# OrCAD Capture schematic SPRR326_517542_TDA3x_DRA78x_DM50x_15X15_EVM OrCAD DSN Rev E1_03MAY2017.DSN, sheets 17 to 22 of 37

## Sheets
17 SH25 - VOUT HDMI OUTPUT: size C; rev: A
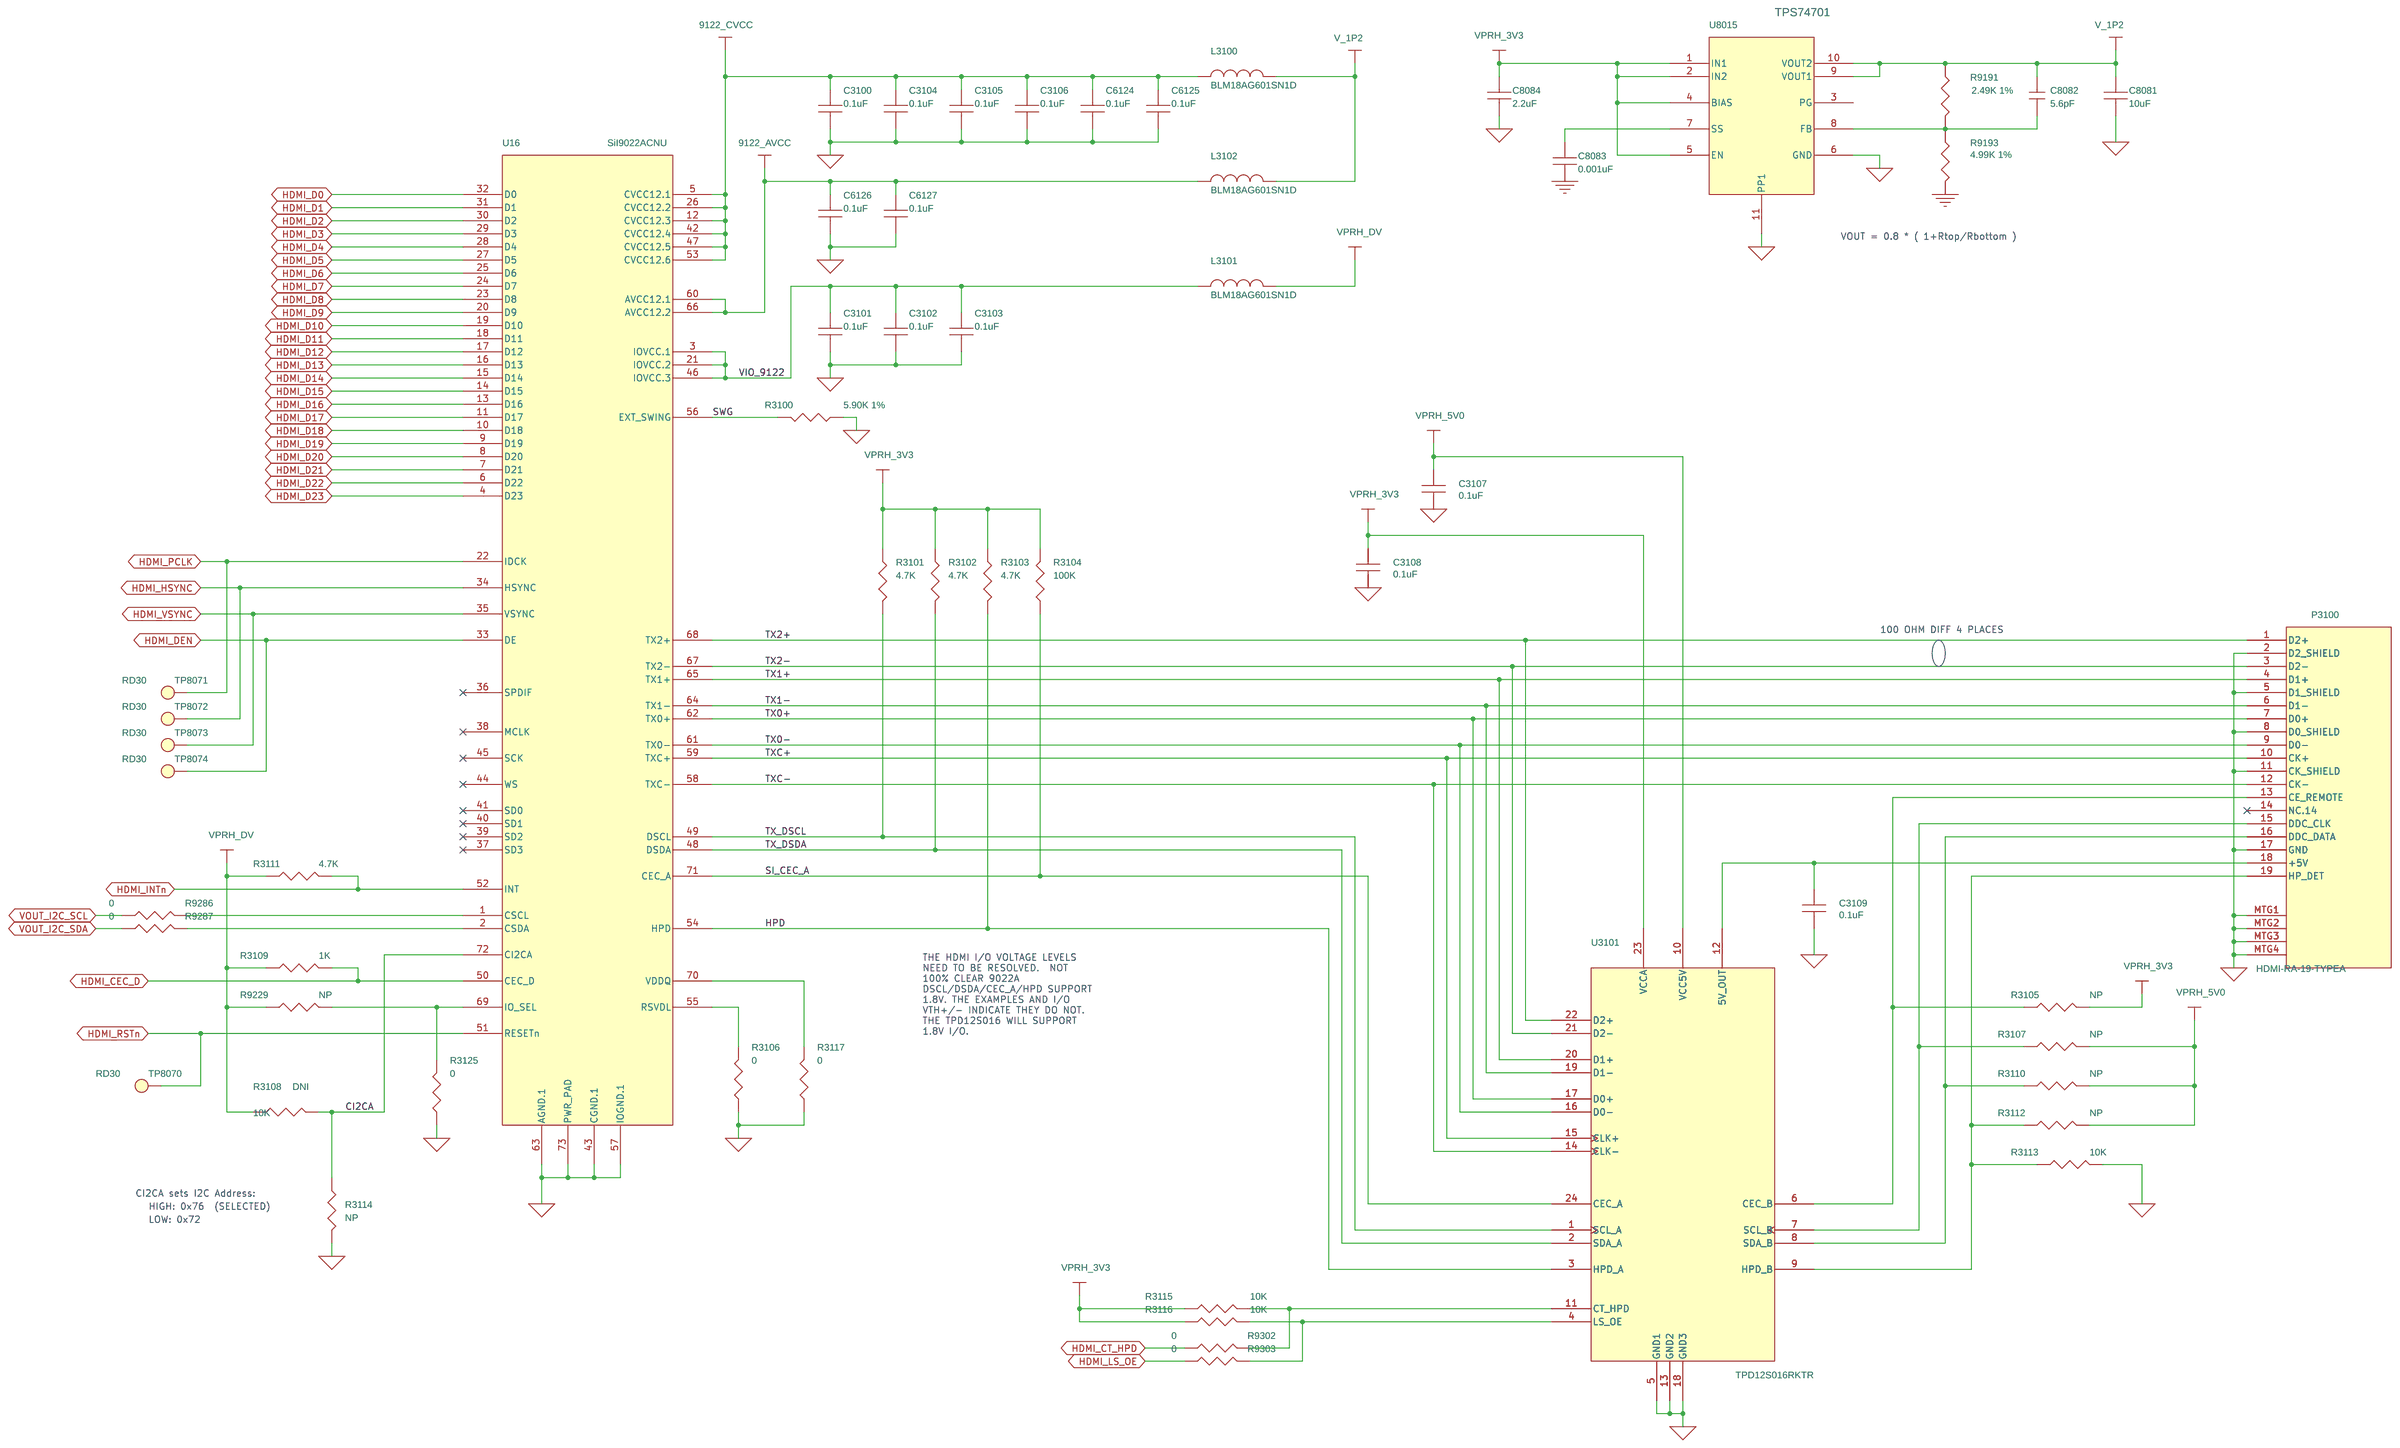
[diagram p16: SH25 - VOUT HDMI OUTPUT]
18 SH26 - VOUT FPD LINK: size C; rev: A
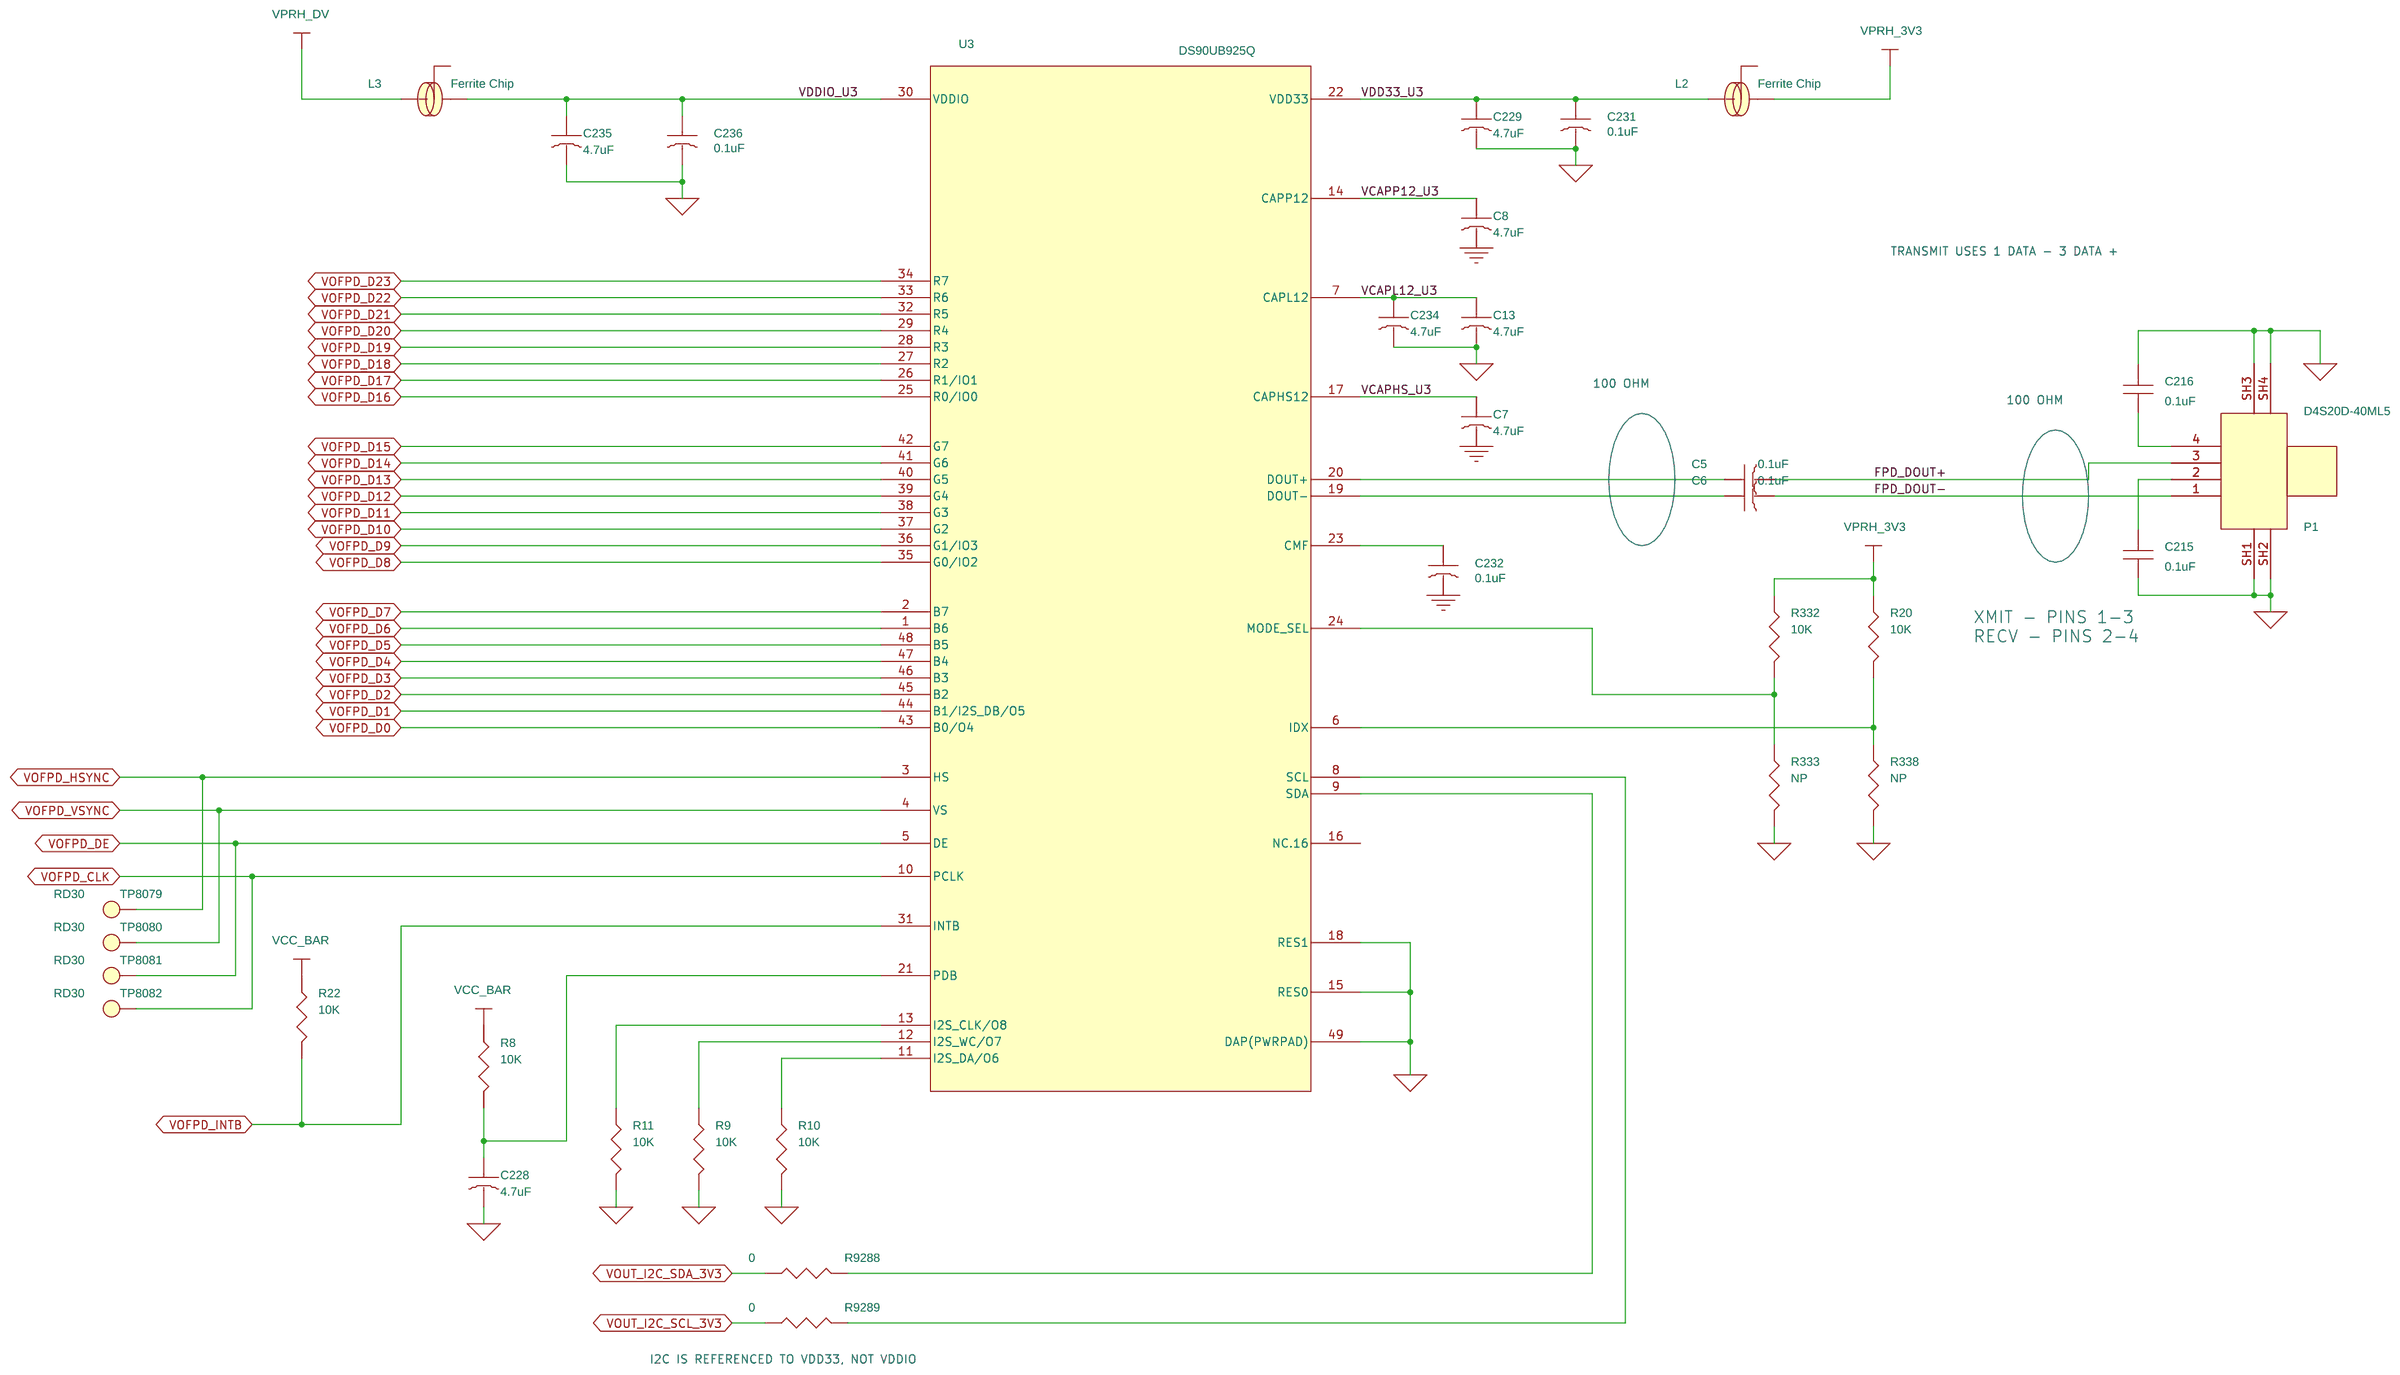
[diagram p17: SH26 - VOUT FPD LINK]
19 SH27 - VIN DS90UH926Q: size C; rev: A
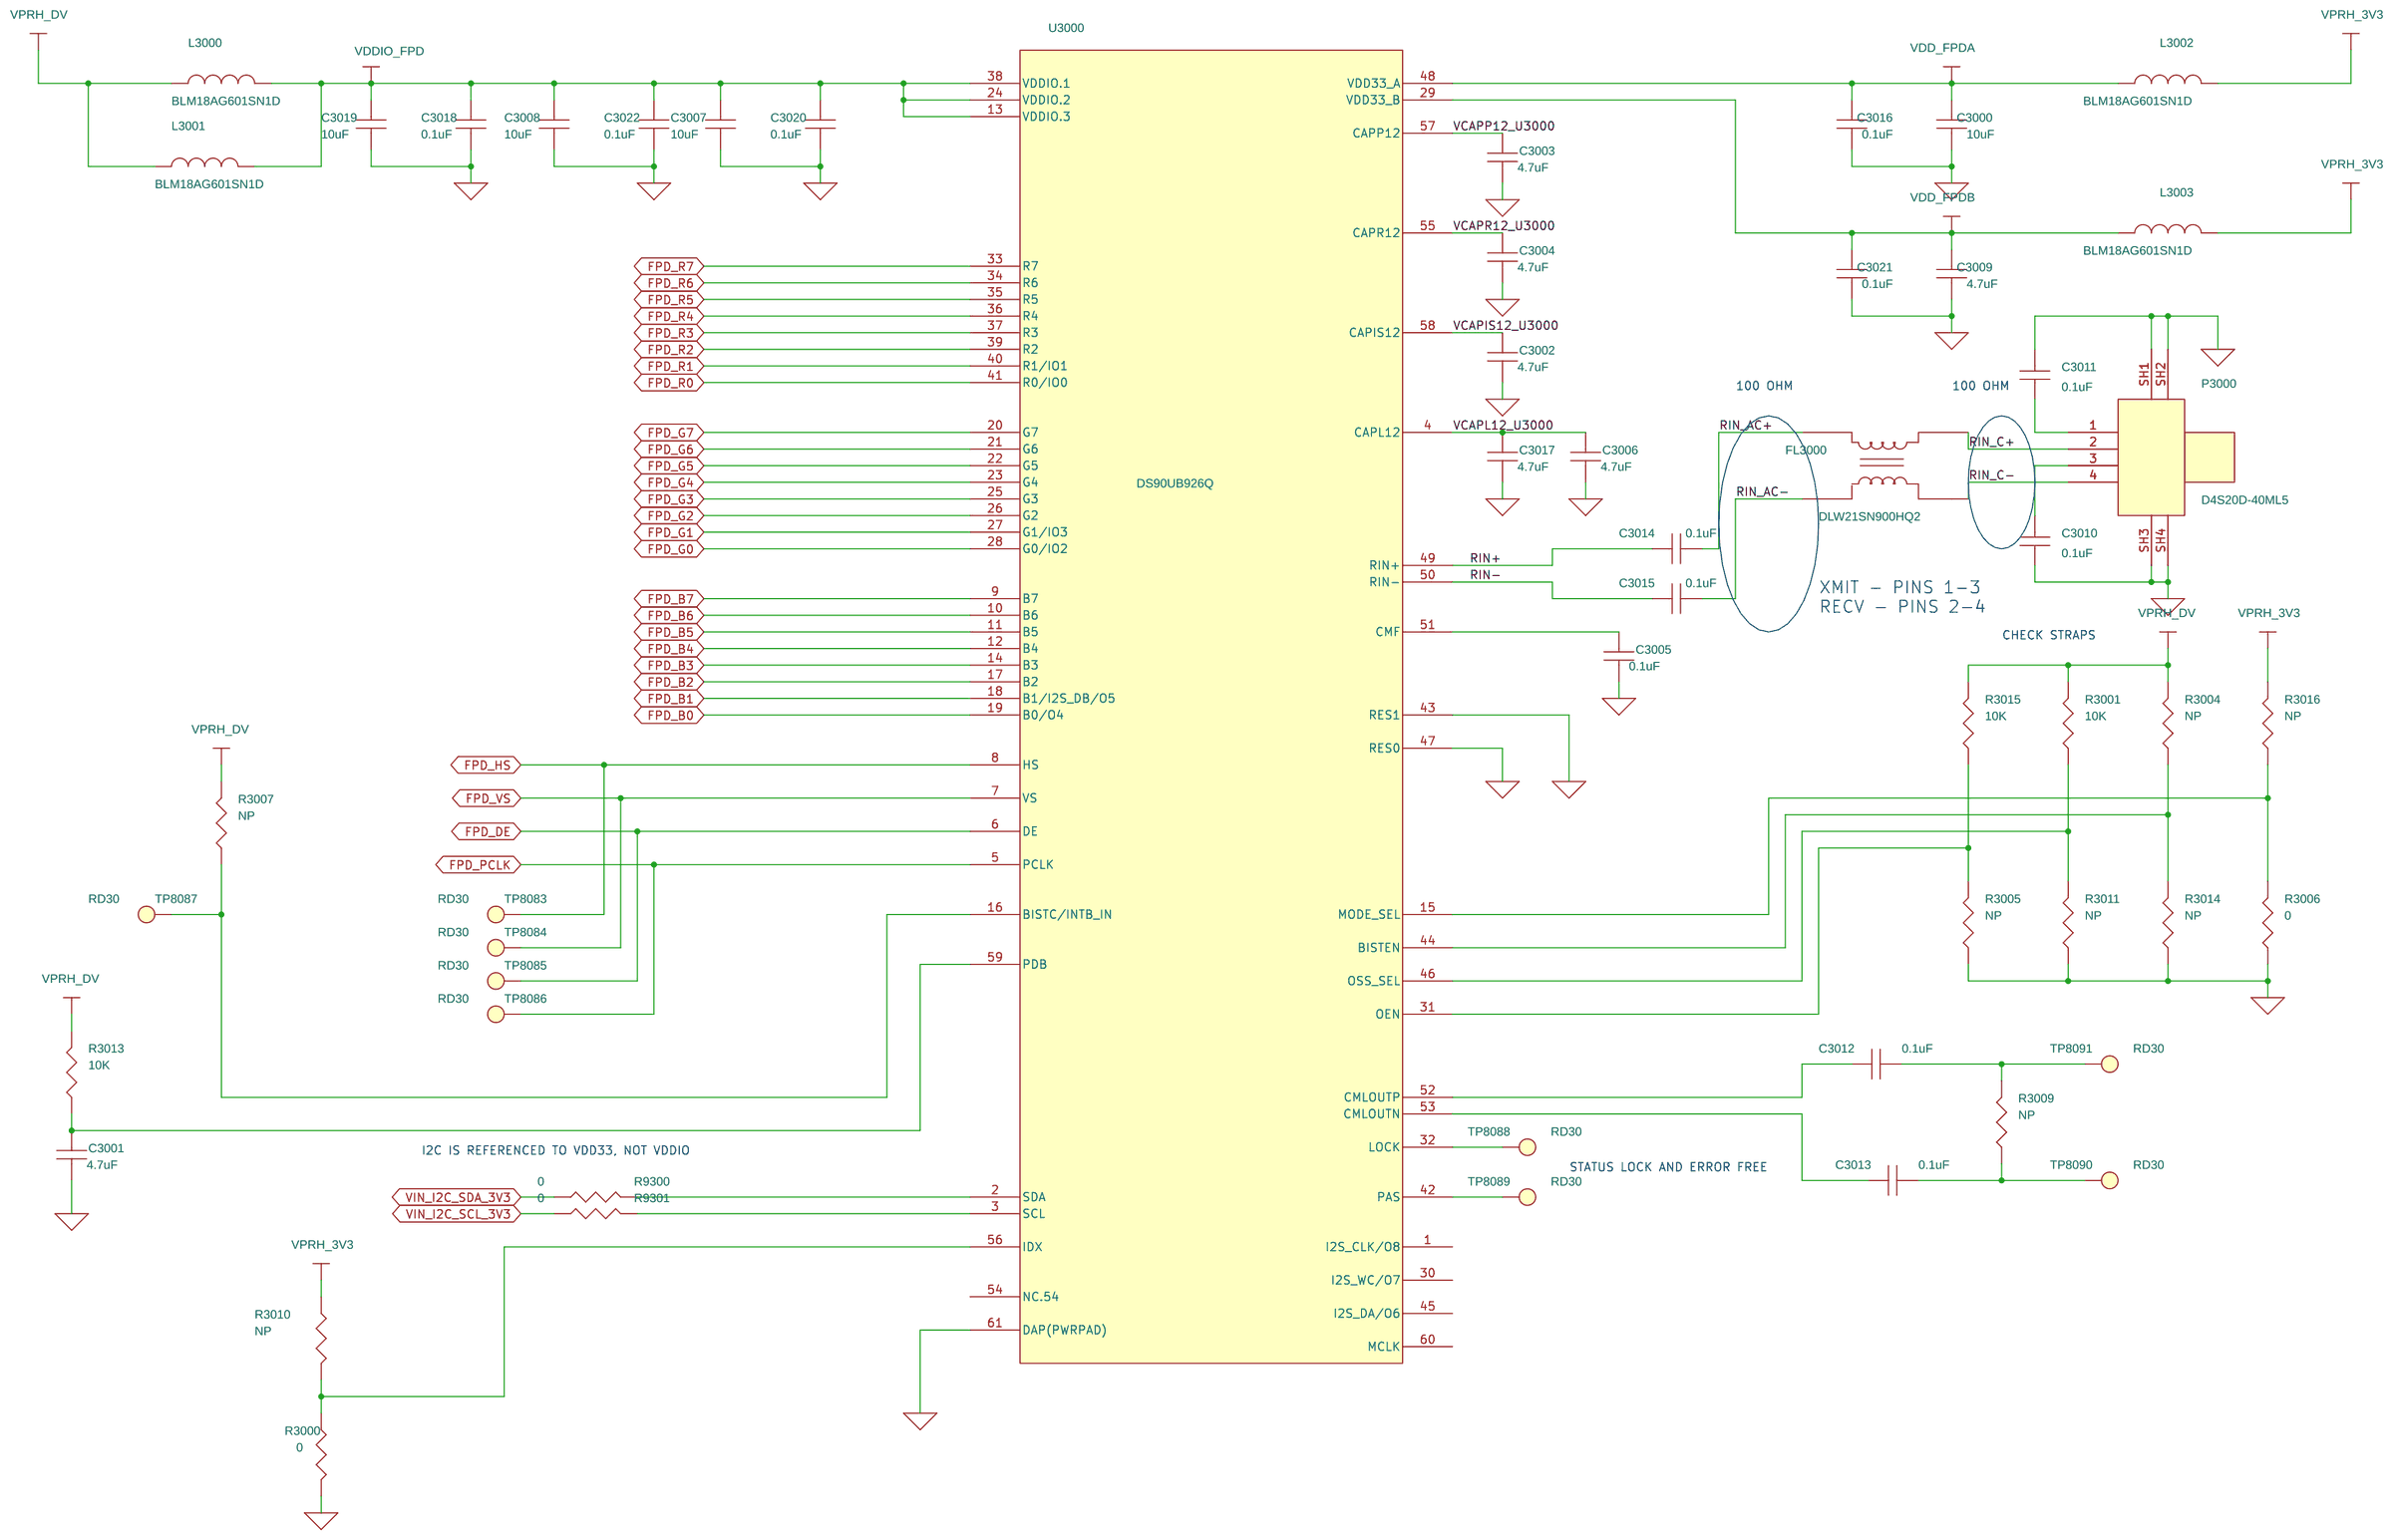
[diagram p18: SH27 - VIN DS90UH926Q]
20 SH28 - VIN CAMERA 1: size C; rev: C1
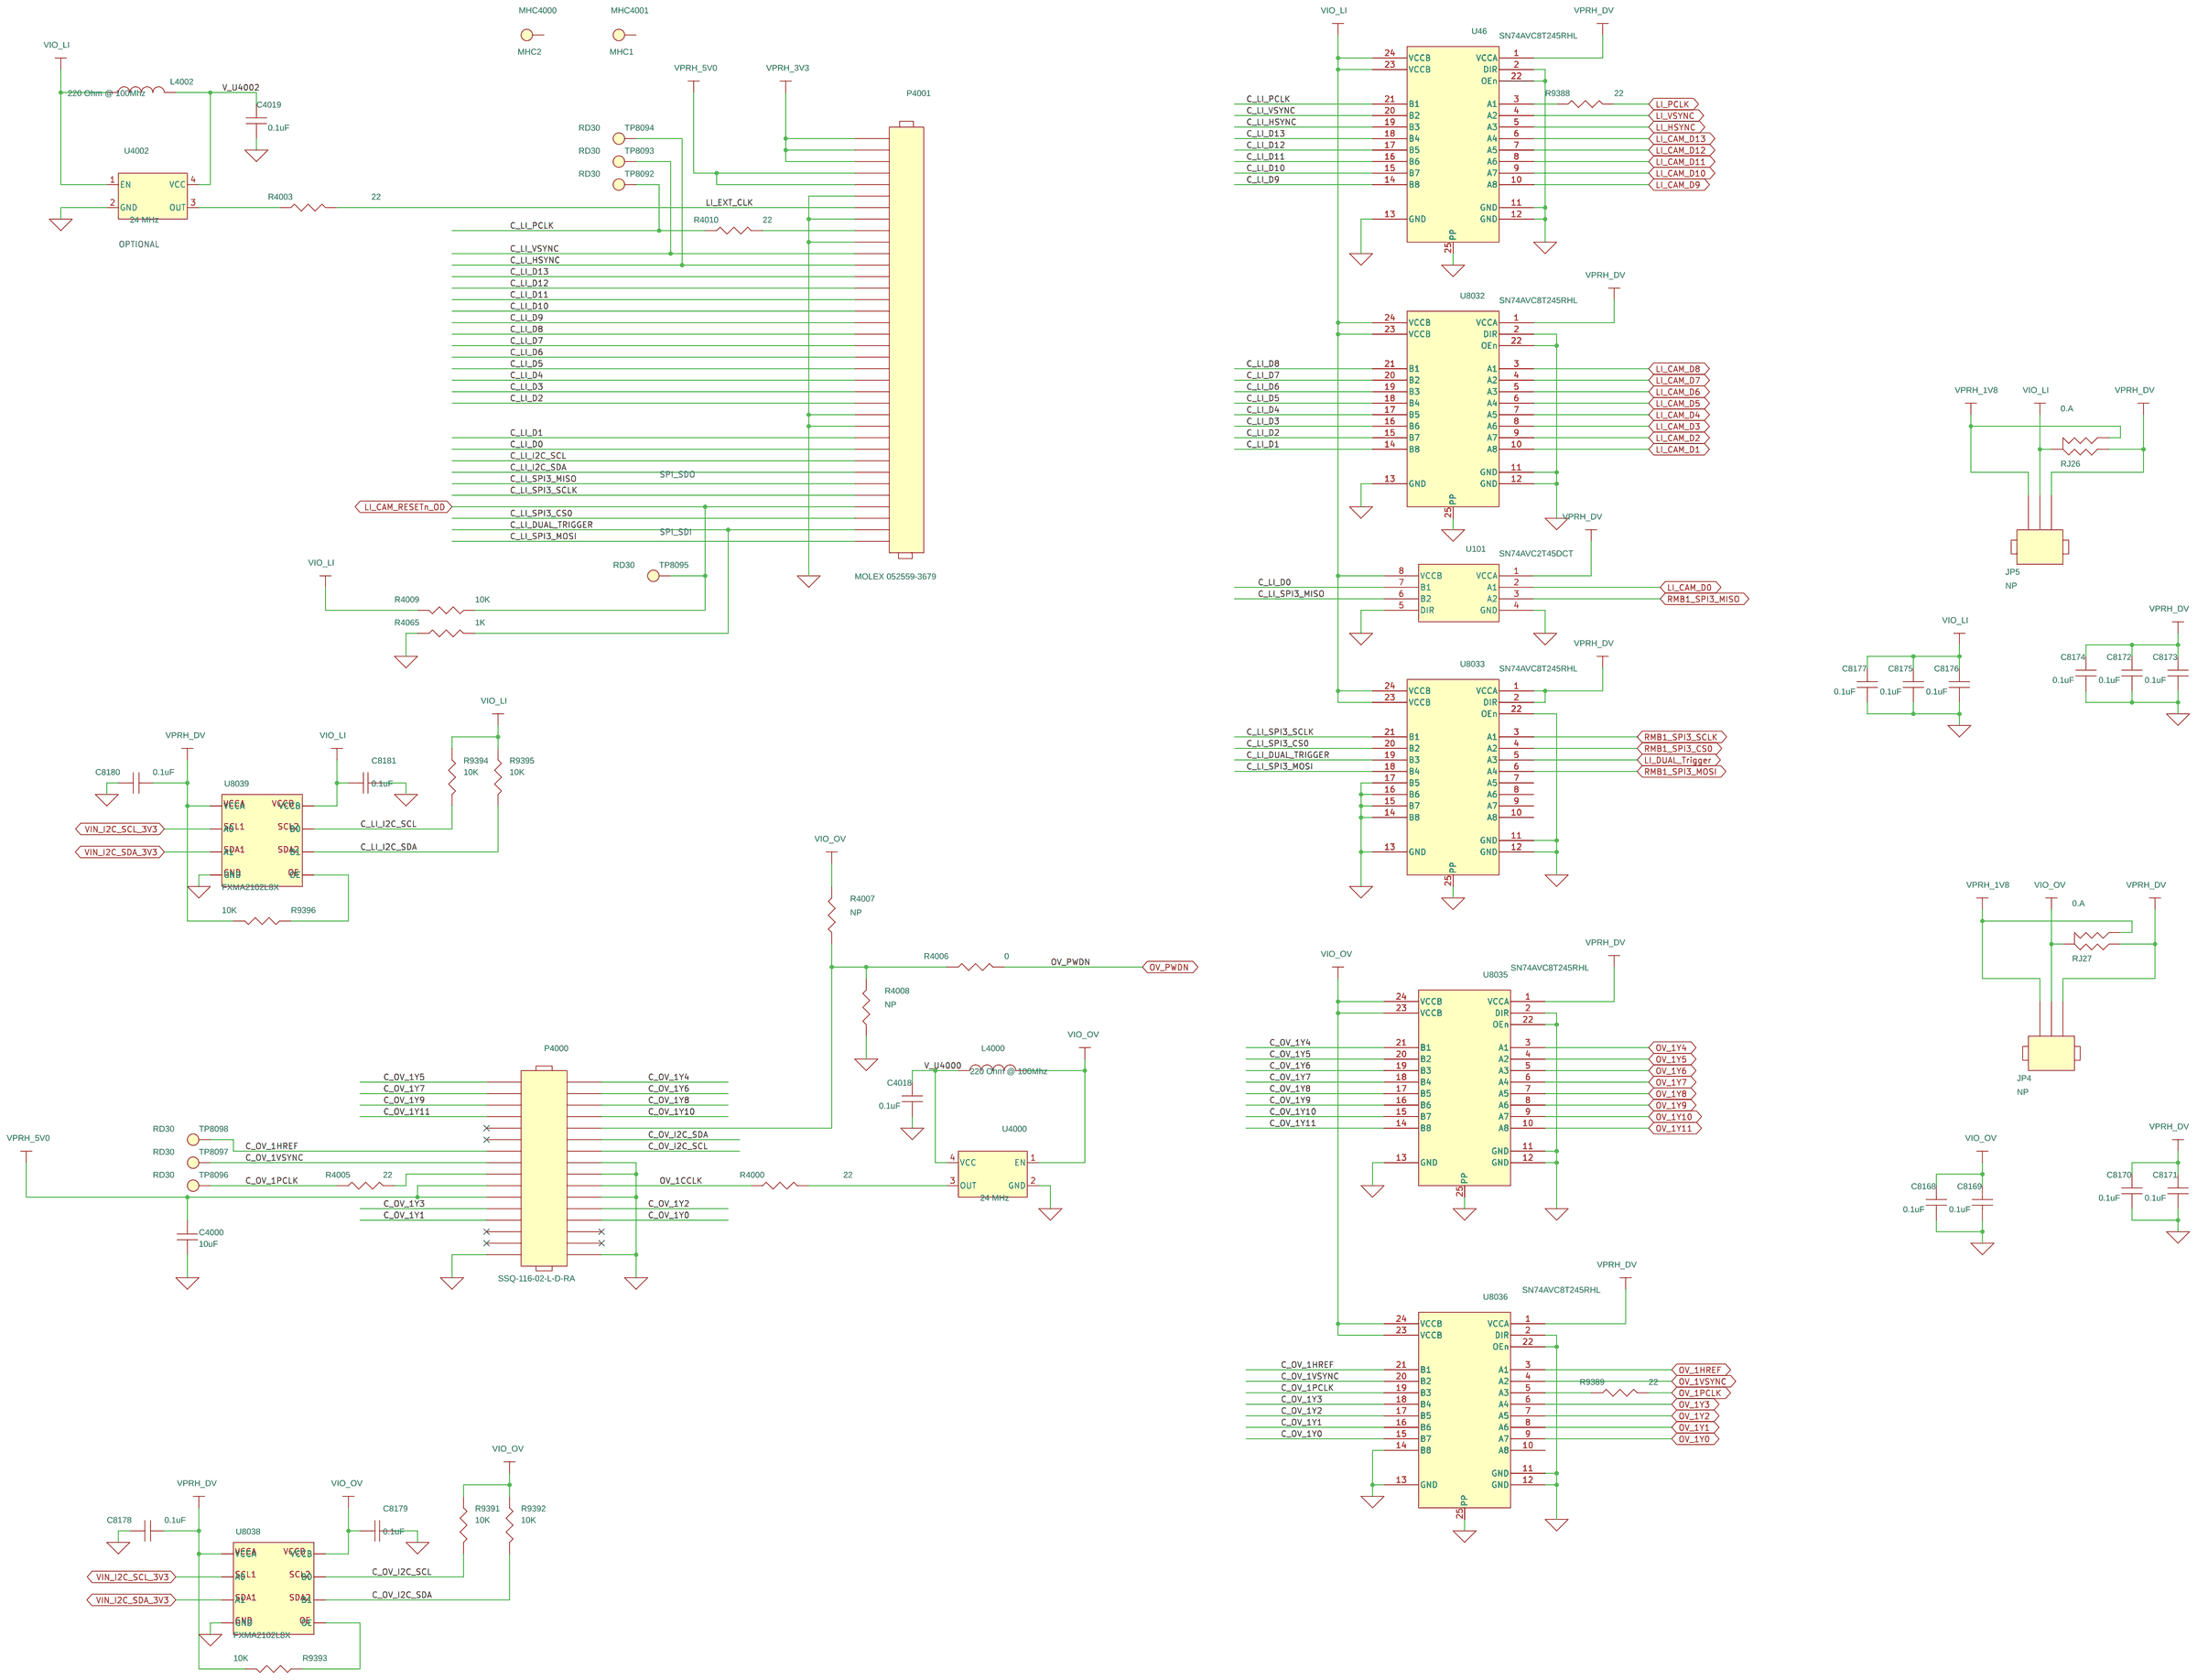
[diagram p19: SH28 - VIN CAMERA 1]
21 SH29 - VIN CAMERA 2: size C; rev: C1
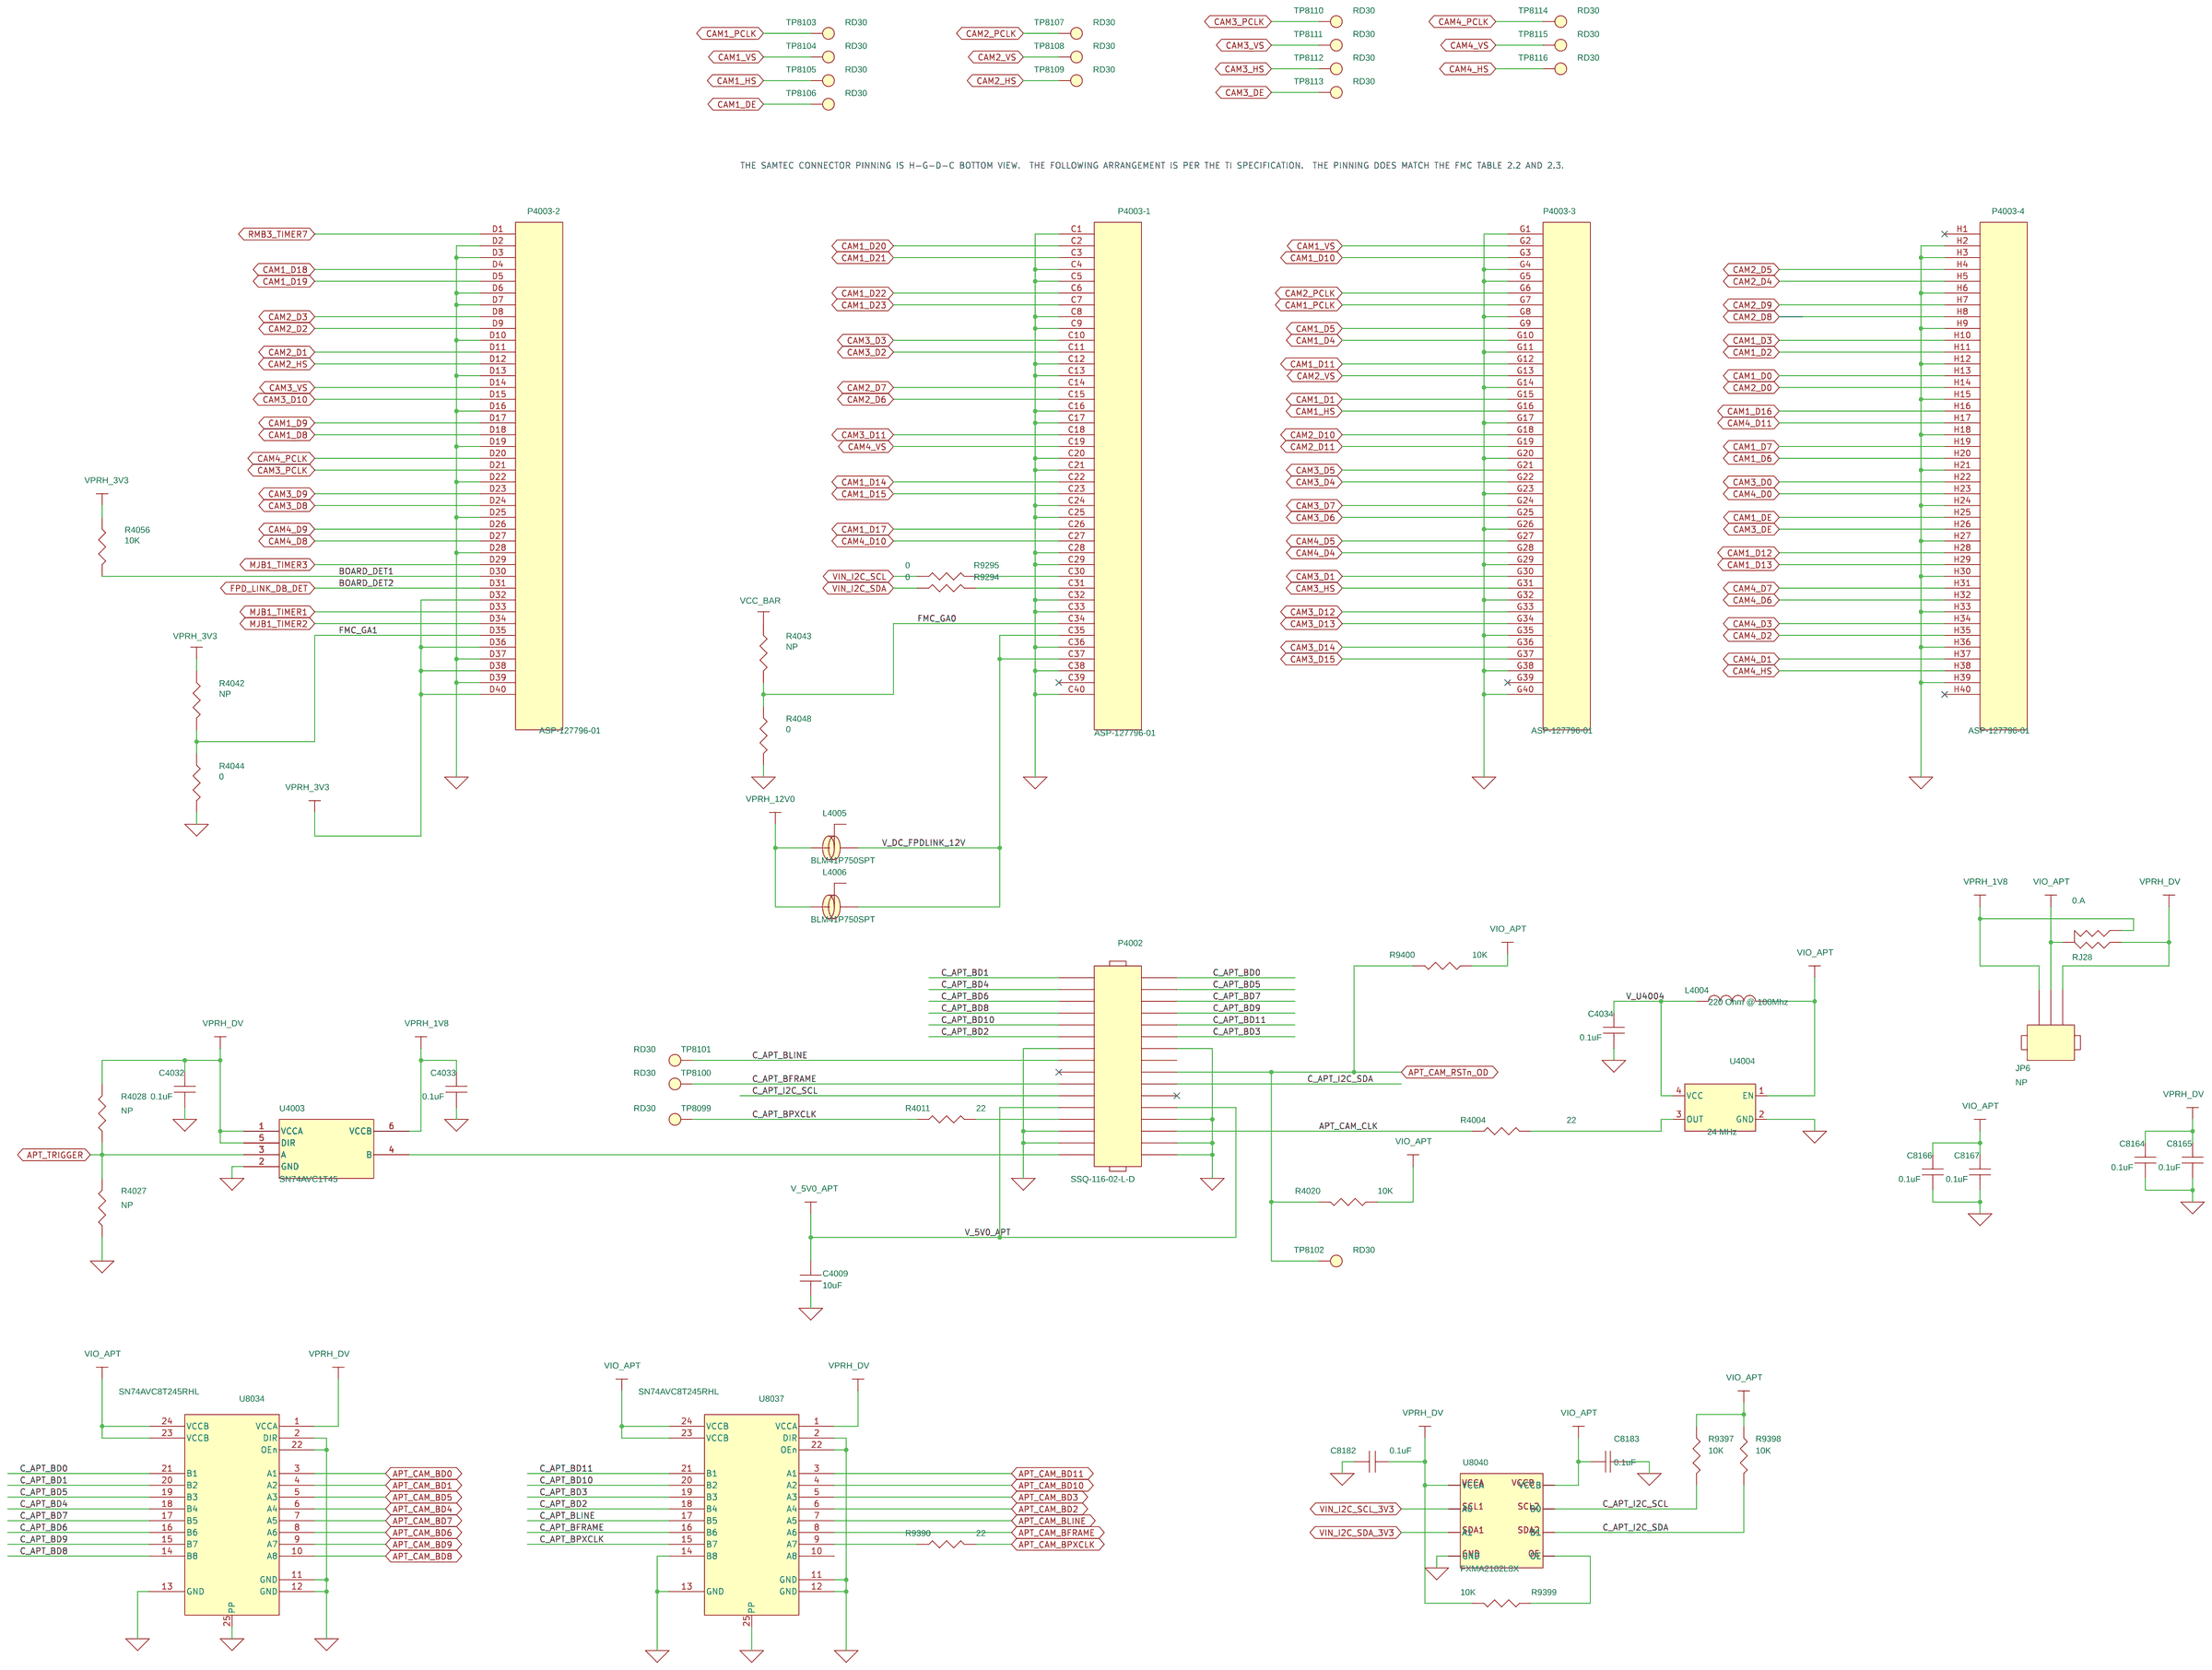
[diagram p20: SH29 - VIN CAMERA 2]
22 SH30 - VIN CSI2: size C; rev: C1
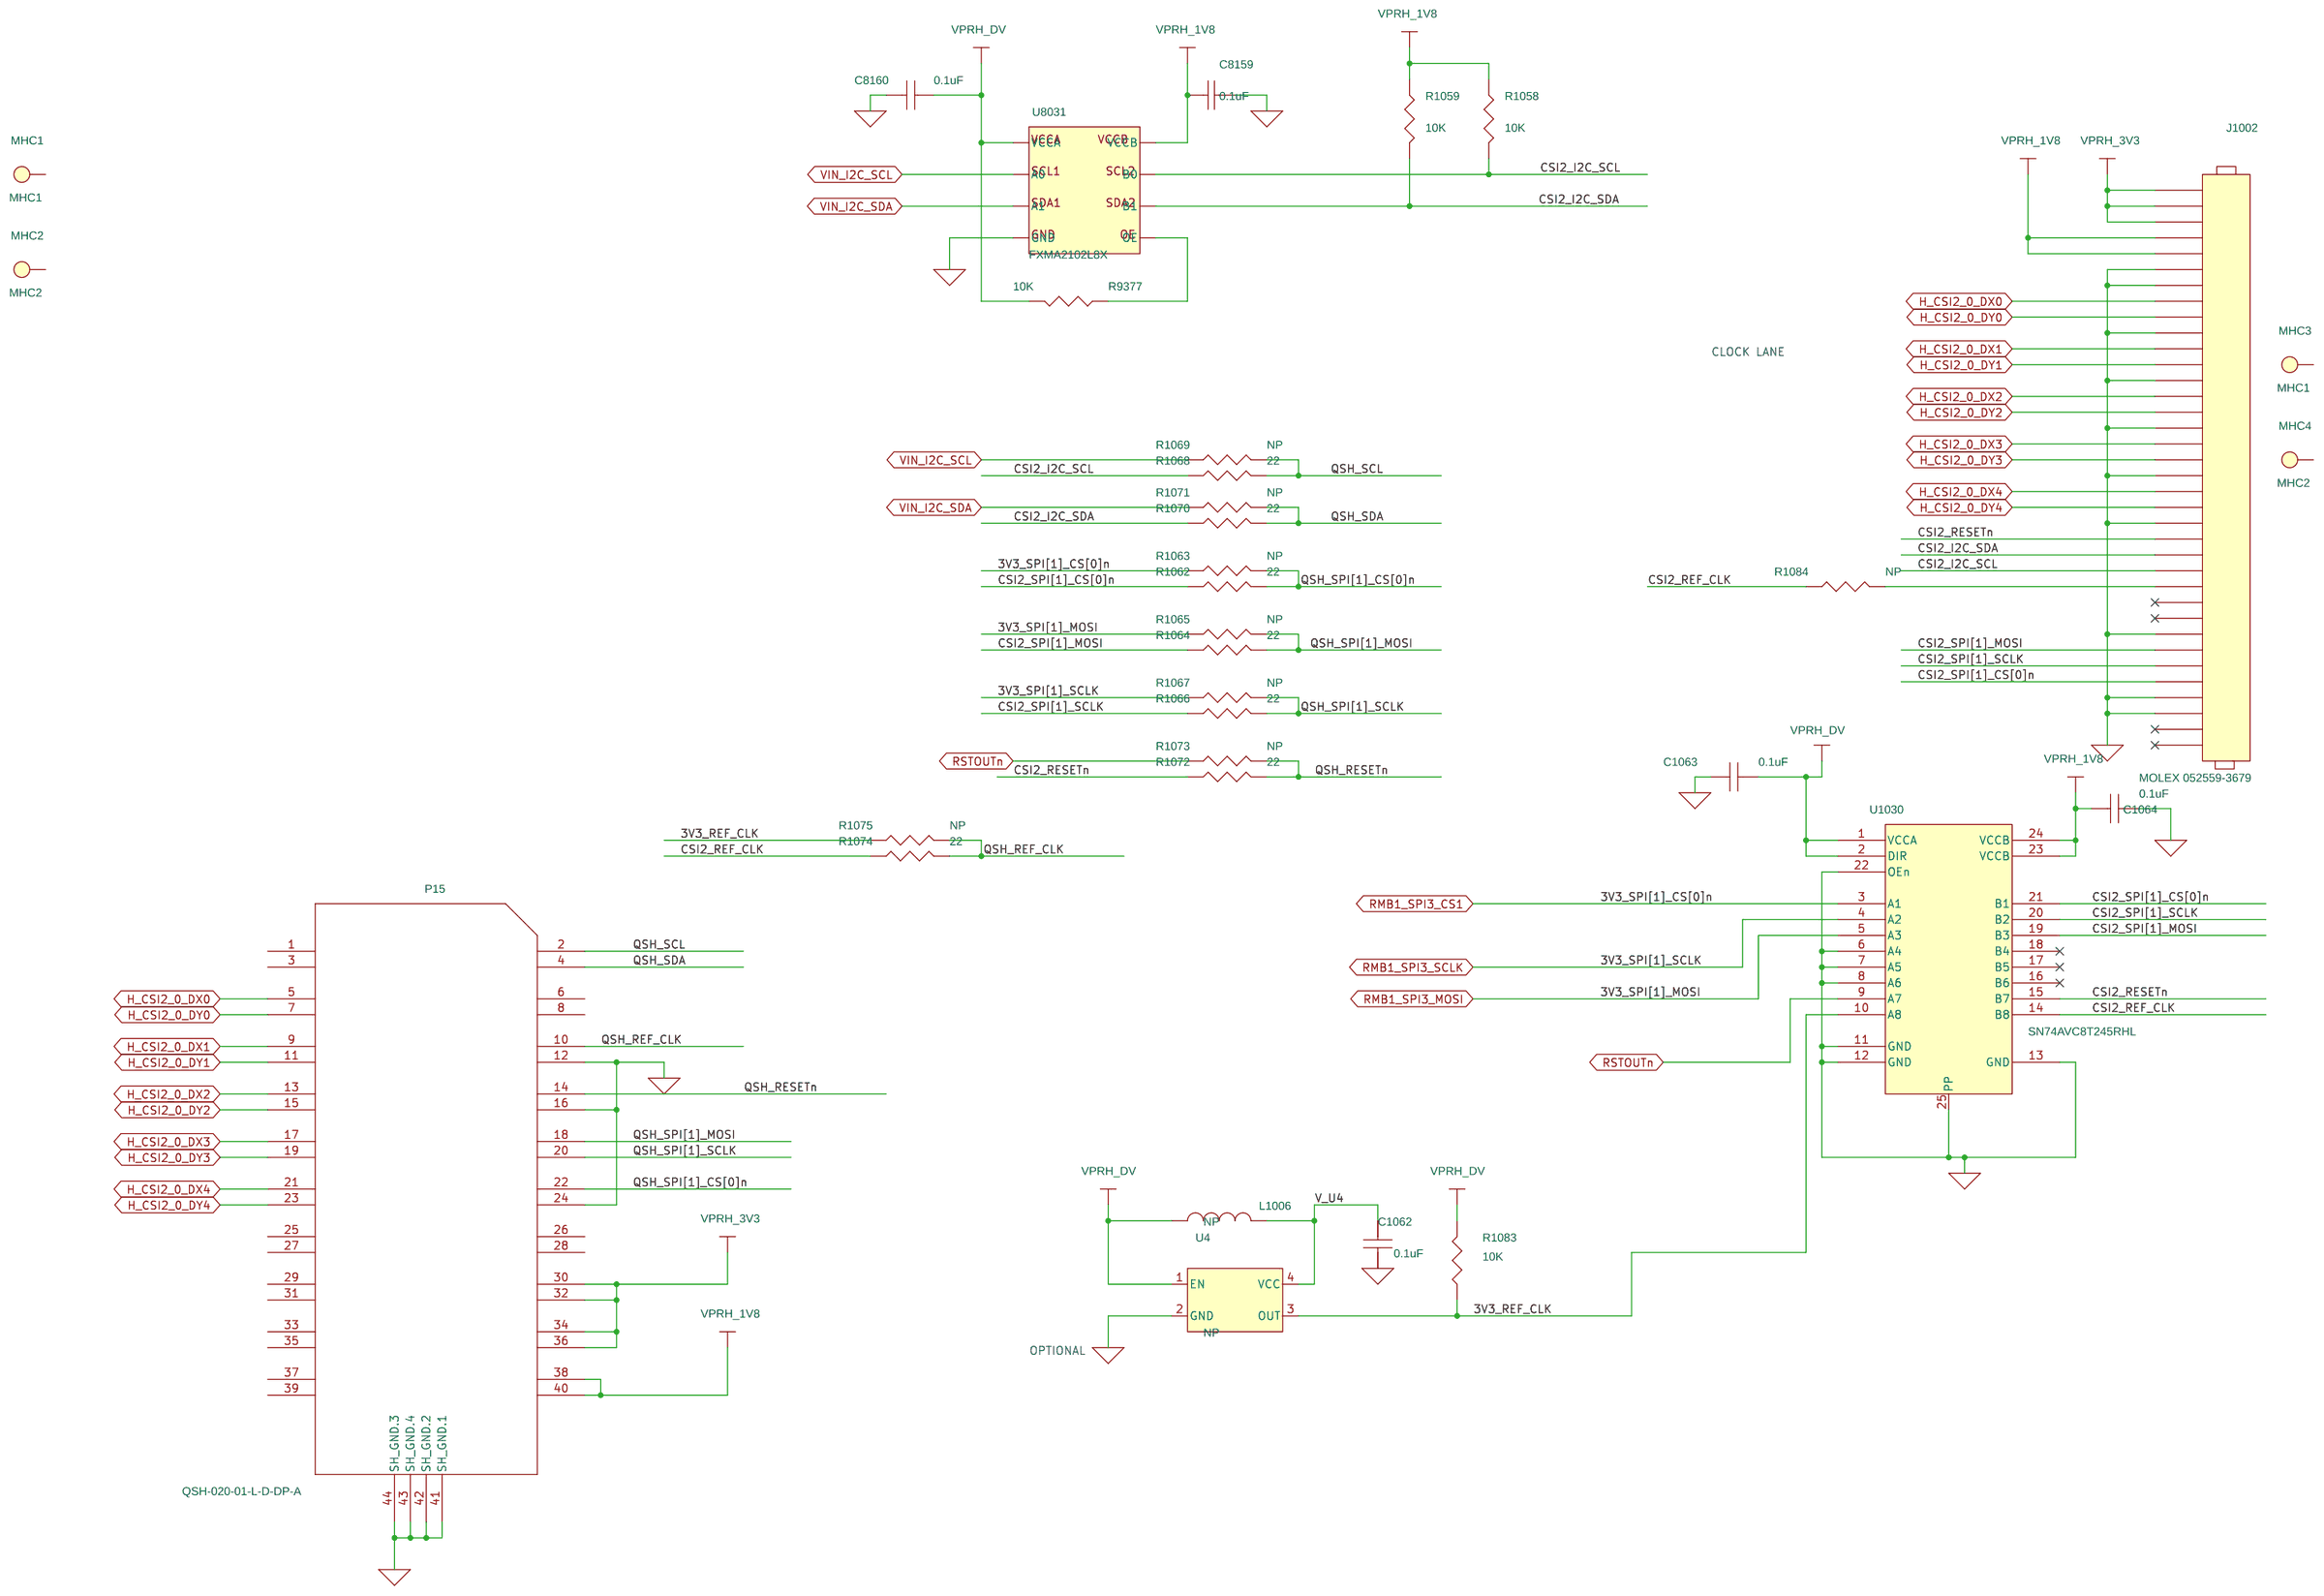
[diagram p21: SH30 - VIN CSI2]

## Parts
sheet SH25 - VOUT HDMI OUTPUT
C3100  0.1uF  [c402-25]
C3101  0.1uF  [c402-25]
C3102  0.1uF  [c402-25]
C3103  0.1uF  [c402-25]
C3104  0.1uF  [c402-25]
C3105  0.1uF  [c402-25]
C3106  0.1uF  [c402-25]
C3107  0.1uF  [c402-25]
C3108  0.1uF  [c402-25]
C3109  0.1uF  [c402-25]
C6124  0.1uF  [c402-25]
C6125  0.1uF  [c402-25]
C6126  0.1uF  [c402-25]
C6127  0.1uF  [c402-25]
C8081  10uF  [c603-35x45]
C8082  5.6pF  [c402-25]
C8083  0.001uF  [c402-25]
C8084  2.2uF  [c603-35x45]
L3100  BLM18AG601SN1D  [l603-35x45]
L3101  BLM18AG601SN1D  [l603-35x45]
L3102  BLM18AG601SN1D  [l603-35x45]
P3100  HDMI-RA-19-TYPEA  [hdmi-smt-w-flange-rdpads]
R3100  5.90K 1%  [r402-25]
R3101  4.7K  [r402-25]
R3102  4.7K  [r402-25]
R3103  4.7K  [r402-25]
R3104  100K  [r402-25]
R3105  NP  [r402-25]
R3106  0  [r402-25]
R3107  NP  [r402-25]
R3108  10K  [r402-25]
R3109  1K  [r402-25]
R3110  NP  [r402-25]
R3111  4.7K  [r402-25]
R3112  NP  [r402-25]
R3113  10K  [r402-25]
R3114  NP  [r402-25]
R3115  10K  [r402-25]
R3116  10K  [r402-25]
R3117  0  [r402-25]
R3125  0  [r402-25]
R9191  2.49K 1%  [r603-35x45]
R9193  4.99K 1%  [r603-35x45]
R9229  NP  [r402-25]
R9286  0  [r201-6p6spc]
R9287  0  [r201-6p6spc]
R9302  0  [r201-6p6spc]
R9303  0  [r201-6p6spc]
TP8070  RD30  [tp-30RD13]
TP8071  RD30  [tp-30RD13]
TP8072  RD30  [tp-30RD13]
TP8073  RD30  [tp-30RD13]
TP8074  RD30  [tp-30RD13]
U16  SiI9022ACNU  [qfn72-10x10]
U3101  TPD12S016RKTR  [rkt24]
U8015  TPS74701  [drc10-11x33]
sheet SH26 - VOUT FPD LINK
C5  0.1uF  [c402-25]
C6  0.1uF  [c402-25]
C7  4.7uF  [C805-35X60]
C8  4.7uF  [C805-35X60]
C13  4.7uF  [C805-35X60]
C215  0.1uF  [c402-25]
C216  0.1uF  [c402-25]
C228  4.7uF  [C805-35X60]
C229  4.7uF  [C805-35X60]
C231  0.1uF  [c402-25]
C232  0.1uF  [c402-25]
C234  4.7uF  [C805-35X60]
C235  4.7uF  [C805-35X60]
C236  0.1uF  [c402-25]
L2  Ferrite Chip  [l603-35x45]
L3  Ferrite Chip  [l603-35x45]
P1  D4S20D-40ML5  [con_mb261]
R8  10K  [r402-25]
R9  10K  [r402-25]
R10  10K  [r402-25]
R11  10K  [r402-25]
R20  10K  [r402-25]
R22  10K  [r402-25]
R332  10K  [r402-25]
R333  NP  [r402-25]
R338  NP  [r402-25]
R9288  0  [r201-6p6spc]
R9289  0  [r201-6p6spc]
TP8079  RD30  [tp-30RD13]
TP8080  RD30  [tp-30RD13]
TP8081  RD30  [tp-30RD13]
TP8082  RD30  [tp-30RD13]
U3  DS90UB925Q  [QFN48-11X35]
sheet SH27 - VIN DS90UH926Q
C3000  10uF  [c805-35x60]
C3001  4.7uF  [C805-35X60]
C3002  4.7uF  [C805-35X60]
C3003  4.7uF  [C805-35X60]
C3004  4.7uF  [C805-35X60]
C3005  0.1uF  [c402-25]
C3006  4.7uF  [C805-35X60]
C3007  10uF  [c805-35x60]
C3008  10uF  [c805-35x60]
C3009  4.7uF  [C805-35X60]
C3010  0.1uF  [c402-25]
C3011  0.1uF  [c402-25]
C3012  0.1uF  [c402-25]
C3013  0.1uF  [c402-25]
C3014  0.1uF  [c402-25]
C3015  0.1uF  [c402-25]
C3016  0.1uF  [c402-25]
C3017  4.7uF  [C805-35X60]
C3018  0.1uF  [c402-25]
C3019  10uF  [c805-35x60]
C3020  0.1uF  [c402-25]
C3021  0.1uF  [c402-25]
C3022  0.1uF  [c402-25]
FL3000  DLW21SN900HQ2  [EMI-36X15-DLW21]
L3000  BLM18AG601SN1D  [l603-35x45]
L3001  BLM18AG601SN1D  [l603-35x45]
L3002  BLM18AG601SN1D  [l603-35x45]
L3003  BLM18AG601SN1D  [l603-35x45]
P3000  D4S20D-40ML5  [con_mb261]
R3000  0  [r402-25]
R3001  10K  [r402-25]
R3004  NP  [r402-25]
R3005  NP  [r402-25]
R3006  0  [r402-25]
R3007  NP  [r402-25]
R3009  NP  [r402-25]
R3010  NP  [r402-25]
R3011  NP  [r402-25]
R3013  10K  [r402-25]
R3014  NP  [r402-25]
R3015  10K  [r402-25]
R3016  NP  [r402-25]
R9300  0  [r201-6p6spc]
R9301  0  [r201-6p6spc]
TP8083  RD30  [tp-30RD13]
TP8084  RD30  [tp-30RD13]
TP8085  RD30  [tp-30RD13]
TP8086  RD30  [tp-30RD13]
TP8087  RD30  [tp-30RD13]
TP8088  RD30  [tp-30RD13]
TP8089  RD30  [tp-30RD13]
TP8090  RD30  [tp-30RD13]
TP8091  RD30  [tp-30RD13]
U3000  DS90UB926Q  [LLP-60_9X9]
sheet SH28 - VIN CAMERA 1
C4000  10uF  [c1206-40x70-POL]
C4018  0.1uF  [c402-25]
C4019  0.1uF  [c402-25]
C8168  0.1uF  [c402-25]
C8169  0.1uF  [c402-25]
C8170  0.1uF  [c402-25]
C8171  0.1uF  [c402-25]
C8172  0.1uF  [c402-25]
C8173  0.1uF  [c402-25]
C8174  0.1uF  [c402-25]
C8175  0.1uF  [c402-25]
C8176  0.1uF  [c402-25]
C8177  0.1uF  [c402-25]
C8178  0.1uF  [c402-25]
C8179  0.1uF  [c402-25]
C8180  0.1uF  [c402-25]
C8181  0.1uF  [c402-25]
JP4  NP  [JUMP1X3-6040]
JP5  NP  [JUMP1X3-6040]
L4000  220 Ohm @ 100Mhz  [l805-35x60]
L4002  220 Ohm @ 100Mhz  [l805-35x60]
MHC4000  MHC2  [MH93-125]
MHC4001  MHC1  [MH93-125]
P4000  SSQ-116-02-L-D-RA  [conn-skt-2x16-ra]
P4001  MOLEX 052559-3679  [conn36-52559]
R4000  22  [r402-25]
R4003  22  [r402-25]
R4005  22  [r402-25]
R4006  0  [r402-25]
R4007  NP  [r402-25]
R4008  NP  [r402-25]
R4009  10K  [r402-25]
R4010  22  [r402-25]
R4065  1K  [r402-25]
R9388  22  [r402-25]
R9389  22  [r402-25]
R9391  10K  [r402-25]
R9392  10K  [r402-25]
R9393  10K  [r402-25]
R9394  10K  [r402-25]
R9395  10K  [r402-25]
R9396  10K  [r402-25]
RJ26  0.A  [JMP402-25]
RJ27  0.A  [JMP402-25]
TP8092  RD30  [tp-30RD13]
TP8093  RD30  [tp-30RD13]
TP8094  RD30  [tp-30RD13]
TP8095  RD30  [tp-30RD13]
TP8096  RD30  [tp-30RD13]
TP8097  RD30  [tp-30RD13]
TP8098  RD30  [tp-30RD13]
U46  SN74AVC8T245RHL  [rhl24-pvqfn-ti]
U101  SN74AVC2T45DCT  [dct8-14x70]
U4000  24 MHz  [OSC4-71X79]
U4002  24 MHz  [OSC4-71X79]
U8032  SN74AVC8T245RHL  [rhl24-pvqfn-ti]
U8033  SN74AVC8T245RHL  [rhl24-pvqfn-ti]
U8035  SN74AVC8T245RHL  [rhl24-pvqfn-ti]
U8036  SN74AVC8T245RHL  [rhl24-pvqfn-ti]
U8038  FXMA2102L8X  [micropak8]
U8039  FXMA2102L8X  [micropak8]
sheet SH29 - VIN CAMERA 2
C4009  10uF  [c1206-40x70-POL]
C4032  0.1uF  [c402-25]
C4033  0.1uF  [c402-25]
C4034  0.1uF  [c402-25]
C8164  0.1uF  [c402-25]
C8165  0.1uF  [c402-25]
C8166  0.1uF  [c402-25]
C8167  0.1uF  [c402-25]
C8182  0.1uF  [c402-25]
C8183  0.1uF  [c402-25]
JP6  NP  [JUMP1X3-6040]
L4004  220 Ohm @ 100Mhz  [l805-35x60]
L4005  BLM41P750SPT  [FB1806-41X70]
L4006  BLM41P750SPT  [FB1806-41X70]
P4002  SSQ-116-02-L-D  [conn2x16-6040]
P4003  ASP-127796-01  [con-skt-asp-40-x4_samtec]  (sections -1,-2,-3,-4)
R4004  22  [r402-25]
R4011  22  [r402-25]
R4020  10K  [r402-25]
R4027  NP  [r402-25]
R4028  NP  [r402-25]
R4042  NP  [r402-25]
R4043  NP  [r402-25]
R4044  0  [r402-25]
R4048  0  [r402-25]
R4056  10K  [r402-25]
R9294  0  [r201-6p6spc]
R9295  0  [r201-6p6spc]
R9390  22  [r402-25]
R9397  10K  [r402-25]
R9398  10K  [r402-25]
R9399  10K  [r402-25]
R9400  10K  [r402-25]
RJ28  0.A  [JMP402-25]
TP8099  RD30  [tp-30RD13]
TP8100  RD30  [tp-30RD13]
TP8101  RD30  [tp-30RD13]
TP8102  RD30  [tp-30RD13]
TP8103  RD30  [tp-30RD13]
TP8104  RD30  [tp-30RD13]
TP8105  RD30  [tp-30RD13]
TP8106  RD30  [tp-30RD13]
TP8107  RD30  [tp-30RD13]
TP8108  RD30  [tp-30RD13]
TP8109  RD30  [tp-30RD13]
TP8110  RD30  [tp-30RD13]
TP8111  RD30  [tp-30RD13]
TP8112  RD30  [tp-30RD13]
TP8113  RD30  [tp-30RD13]
TP8114  RD30  [tp-30RD13]
TP8115  RD30  [tp-30RD13]
TP8116  RD30  [tp-30RD13]
U4003  SN74AVC1T45  [DCK-17X60-6]
U4004  24 MHz  [OSC4-71X79]
U8034  SN74AVC8T245RHL  [rhl24-pvqfn-ti]
U8037  SN74AVC8T245RHL  [rhl24-pvqfn-ti]
U8040  FXMA2102L8X  [micropak8]
sheet SH30 - VIN CSI2
C1062  0.1uF  [c402-25]
C1063  0.1uF  [c402-25]
C1064  0.1uF  [c402-25]
C8159  0.1uF  [c402-25]
C8160  0.1uF  [c402-25]
J1002  MOLEX 052559-3679  [conn36-52559-mirror]
L1006  NP  [l805-35x60]
MHC1  MHC1  [MH93-125]
MHC2  MHC2  [MH93-125]
MHC3  MHC1  [MH93-125]
MHC4  MHC2  [MH93-125]
P15  QSH-020-01-L-D-DP-A  [qsh-020-dp-A]
R1058  10K  [r402-25]
R1059  10K  [r402-25]
R1062  22  [r402-25]
R1063  NP  [r402-25]
R1064  22  [r402-25]
R1065  NP  [r402-25]
R1066  22  [r402-25]
R1067  NP  [r402-25]
R1068  22  [r402-25]
R1069  NP  [r402-25]
R1070  22  [r402-25]
R1071  NP  [r402-25]
R1072  22  [r402-25]
R1073  NP  [r402-25]
R1074  22  [r402-25]
R1075  NP  [r402-25]
R1083  10K  [r402-25]
R1084  NP  [r402-25]
R9377  10K  [r402-25]
U4  NP  [OSC4-71X79]
U1030  SN74AVC8T245RHL  [rhl24-pvqfn-ti]
U8031  FXMA2102L8X  [micropak8]

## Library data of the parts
C3100-C3106 C6124-C6127 = 0402_0r1uf_x7r_10v_10: Part #: 104446-1100R
C1063 C1064 C3012 C3013 C3107-C3109 = CAP_NP: Part #: 104446-1100R
C8081 = CAP_NP: Part #: 102963-0101R
C8082 = Cap_100nF_Cermc_16V_10%_603_0: 3pF Capacitor, Ceramic, 16V, 10%, 0402; Part #: 101782-1565R; PartName: Cap 3pF Cermc 16V 10% 402; SD PCB Footprint: EIA0402
C8083 = CAP_NP: Part #: 102058-1102R
C8084 = CAP_NP: Part #: 104448-0220R
L3100-L3102 = 0603_300_100mhz_cb_230ma_25: Part #: 101858-6001R
P3100 = HDMI-RA-19_0: Part #: 103169-0001R
R3100 = RES_0: Part #: 102145-5902R
R3101 = 47_2.5K_0402: Res,47.2K-ohm,1%,0.063W,0402; DES: Res,47.2K-ohm,1%,0.063W,0402; Manufacturer: Rohm; Order#: MCR01MZSF4752; PN: MCR01MZSF4752; Part #: 102145-4702R
R3102 R3103 R3111 = 0402_4r7k_1: RES,4.7K-OHM,1%,0.063W,0402; MANUFACTURER: KOA; ORDER#: RK73H1ELTD4701F; Part #: 102145-4702R
R3104 = 0402_100k_2: Part #: 101370-1004R
R333 R338 R3004 R3005 R3007 R3009-R3011 R3014 R3016 R3105 R3107 R3110 R3112 = R: Part #: R0402-NOPOP
R3106 R3117 R3125 = 272-0494-000_2: Part #: 101370-0001R
R3108 = 0402_10k_1: Res,10K-ohm,1%,0.063W,0402; INSTALLED: DNI; Manufacturer: Panasonic; Order#: ERJ2RKF1002X; PN: ERJ2RKF1002X; Part #: 101370-1003R
R3109 = 0402_1k_1: Part #: 101370-1002R
R8-R11 R20 R22 R332 R1083 R3001 R3013 R3015 R3113 R3115 R3116 R9377 R9391-R9399 = R: Part #: 101370-1003R
R3114 R9229 = 0402_1k_1: Part #: R0402-NOPOP
R9191 = R_3: Part #: 100642-2492R
R9193 = R_3: Part #: 100642-4992R
R9286-R9289 R9294 R9295 R9300-R9303 = R_1: Part #: 103158-0001R
TP8070-TP8074 TP8079-TP8116 = TESTPOINT: Part #: TP-30RD13-NO-POP
U16 = SiI9022AQFN_0: Part #: 103347-0001R
U3101 = TPD12S016RKTR_QFN24_3: Part #: 103797-0001R
U8015 = U-TPS78601_AJUST_-_1_0.5A_LDO: Part #: 102752-0001R
C5 C6 C231 C232 C236 = CAP: Part #: 104446-1100R
C7 C8 C13 C228 C229 C234 C235 = CAP: Part #: 101063-0470R
C215 C216 C3005 C3010 C3011 C3014-C3016 C3018 C3020-C3022 = CAP_0603: Part #: 104446-1100R
L2 L3 = FERRITE_CHIP_0: Part #: 101858-2201R
P1 P3000 = D4S20D-40ML5-Y: Part #: 104234-0001R
U3 = DS90UH925Q_1: Part #: 104304-0001R
C3000 C3007 C3008 C3019 = CAP_0603: Part #: 104447-0101R
C3001-C3004 C3006 C3009 C3017 = CAP_0603: Part #: 101063-0470R
FL3000 = DLW21SN900HQ2: Part #: 104184-9000R
L3000-L3003 = INDUCTOR_0: Part #: 101858-6001R
R3000 R3006 R4006 = R: Part #: 101370-0001R
U3000 = DS90UH926Q_5: Part #: 104305-0001R
C4000 C4009 = CAP_NP: Part #: 101003-0101R
C1062 C4018 C4019 C4032-C4034 C8164-C8177 = CAP_NP_1: Part #: 104446-1100R
C8160 C8178 C8180 C8182 = CAP_.1_uF_10%_0603: Part #: 104446-1100R
C8159 C8179 C8181 C8183 = X5R_100nF_6V3: Part #: 104446-1100R
JP4-JP6 = HEADER_3: Part #: NO-POP
L4000 L4002 L4004 = INDUCTOR_0: Part #: 101228-2201R
MHC1-MHC4 MHC4000 MHC4001 = TESTPOINT: Part #: NO-POP
P4000 = HEADER_16X2: Part #: 104268-0016R
J1002 P4001 = HEADER_36: Part #: 103723-0036R
R4000 R4003-R4005 R4010 R4011 R9388-R9390 = RESISTOR: Part #: 101370-2200R
R4007 R4008 R4027 R4028 = RESISTOR: Part #: R0402-NOPOP
R1058 R1059 R4009 R4020 R9400 = RESISTOR_0: Part #: 101370-1003R
R4065 = R: Part #: 101370-1002R
RJ26-RJ28 = RJUMP3: Part #: 101370-0001R
U46 U8032-U8037 = SN74AVC8T245_1: Part #: 102708-0001R
U101 = SN74AVC2T45DCT: Part #: 102051-0001R
U4000 U4002 U4004 = OSC4_SM_0: Part #: 100983-0024R; SD PCB Footprint: CB3LV
U8031 U8038-U8040 = FXMA2102UMX_0: GPAO_ART: 05600047080AA; Part #: 104458-0001R
L4005 L4006 = FERRITE_CHIP: Part #: 101126-0001R; Spectrum Part#: 101126-0001
P4002 = HEADER_16X2: Part #: 104269-0016R
P4003 = ASP-127796-01_0: Part #: 104256-0040R
R4042 R4043 = R_0: Part #: R0402-NOPOP
R4044 R4048 = R_0: Part #: 101370-0001R
R4056 = R_1: Part #: 101370-1003R
U4003 = TMP_095528: Single-Bit Dual Voltage Translator; MfrNum: SN74AVC1T45DBV; Part #: 102156-0001R; TI Footprint: SOT-23
L1006 = INDUCTOR_0: Part #: L0805-NOPOP
P15 = QSH-020-01-L-D-DP-A: Part #: 103429-0020R
R1062 R1064 R1066 R1068 R1070 R1072 R1074 = R_1: Part #: 101370-2200R
R1063 R1065 R1067 R1069 R1071 R1073 R1075 R1084 = R_1: Part #: R0402-NOPOP
U4 = OSC4_SM_0: Part #: NO-POP; SD PCB Footprint: CB3LV
U1030 = SN74AVC8T245_0: Part #: 102708-0001R

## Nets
3V3_REF_CLK: R1075.1 R1083.1 U4.3(OUT) U1030.10(A8)
GND: C7.2 C8.2 C13.2 C215.1 C216.2 C228.2 C229.2 C231.2 C232.2 C234.2 C235.2 C236.2 C1062.2 C1063.1 C1064.2 C3000.2 C3001.2 C3002.2 C3003.2 C3004.2 C3005.2 C3006.2 C3007.2 C3008.2 C3009.2 C3010.1 C3011.2 C3016.2 C3017.2 C3018.2 C3019.2 C3020.2 C3021.2 C3022.2 C3100.2 C3101.2 C3102.2 C3103.2 C3104.2 C3105.2 C3106.2 C3107.2 C3108.2 C3109.2 C4000.2 C4009.2 C4018.2 C4019.2 C4032.2 C4033.2 C4034.2 C6124.2 C6125.2 C6126.2 C6127.2 C8081.2 C8083.2 C8084.2 C8159.1 C8160.2 C8164.2 C8165.2 C8166.2 C8167.2 C8168.2 C8169.2 C8170.2 C8171.2 C8172.2 C8173.2 C8174.2 C8175.2 C8176.2 C8177.2 C8178.2 C8179.1 C8180.2 C8181.1 C8182.2 C8183.1 J1002.6 J1002.7 J1002.10 J1002.13 J1002.16 J1002.19 J1002.22 J1002.29 J1002.33 J1002.34 P1.SH1 P1.SH2 P1.SH3 P1.SH4 P15.12 P15.16 P15.24 P15.41(SH_GND.1) P15.42(SH_GND.2) P15.43(SH_GND.4) P15.44(SH_GND.3) P3000.SH1 P3000.SH2 P3000.SH3 P3000.SH4 P3100.2(D2_SHIELD) P3100.5(D1_SHIELD) P3100.8(D0_SHIELD) P3100.11(CK_SHIELD) P3100.17(GND) P3100.MTG1 P3100.MTG2 P3100.MTG3 P3100.MTG4 P4000.16 P4000.18 P4000.22 P4000.31 P4000.32 P4001.6 P4001.8 P4001.10 P4001.25 P4001.26 P4002.13 P4002.14 P4002.26 P4002.27 P4002.29 P4002.30 P4002.32 P4003.C1 P4003.C4 P4003.C5 P4003.C8 P4003.C9 P4003.C12 P4003.C13 P4003.C16 P4003.C17 P4003.C20 P4003.C21 P4003.C24 P4003.C25 P4003.C28 P4003.C29 P4003.C32 P4003.C33 P4003.C36 P4003.C38 P4003.C40 P4003.D2 P4003.D3 P4003.D6 P4003.D7 P4003.D10 P4003.D13 P4003.D16 P4003.D19 P4003.D22 P4003.D25 P4003.D28 P4003.D37 P4003.D39 P4003.G1 P4003.G4 P4003.G5 P4003.G8 P4003.G11 P4003.G14 P4003.G17 P4003.G20 P4003.G23 P4003.G26 P4003.G29 P4003.G32 P4003.G35 P4003.G38 P4003.G40 P4003.H2 P4003.H3 P4003.H6 P4003.H9 P4003.H12 P4003.H15 P4003.H18 P4003.H21 P4003.H24 P4003.H27 P4003.H30 P4003.H33 P4003.H36 P4003.H39 R9.2 R10.2 R11.2 R333.2 R338.2 R3000.2 R3005.2 R3006.2 R3011.2 R3014.2 R3100.1 R3106.2 R3113.2 R3114.1(P1) R3117.2 R3125.2 R4008.2 R4027.2 R4044.2 R4048.2 R4065.2 R9193.2 U3.15(RES0) U3.18(RES1) U3.49(DAP(PWRPAD)) U4.2(GND) U16.43(CGND.1) U16.57(IOGND.1) U16.63(AGND.1) U16.73(PWR_PAD) U46.2(DIR) U46.11(GND) U46.12(GND) U46.13(GND) U46.22(OEn) U46.25(PP) U101.4(GND) U101.5(DIR) U1030.6(A4) U1030.7(A5) U1030.8(A6) U1030.11(GND) U1030.12(GND) U1030.13(GND) U1030.22(OEn) U1030.25(PP) U3000.43(RES1) U3000.47(RES0) U3000.61(DAP(PWRPAD)) U3101.5(GND1) U3101.13(GND2) U3101.18(GND3) U4000.2(GND) U4002.2(GND) U4003.2(GND) U4004.2(GND) U8015.6(GND) U8015.11(PP1) U8031.4(GND) U8032.2(DIR) U8032.11(GND) U8032.12(GND) U8032.13(GND) U8032.22(OEn) U8032.25(PP) U8033.11(GND) U8033.12(GND) U8033.13(GND) U8033.14(B8) U8033.15(B7) U8033.16(B6) U8033.17(B5) U8033.22(OEn) U8033.25(PP) U8034.2(DIR) U8034.11(GND) U8034.12(GND) U8034.13(GND) U8034.22(OEn) U8034.25(PP) U8035.2(DIR) U8035.11(GND) U8035.12(GND) U8035.13(GND) U8035.22(OEn) U8035.25(PP) U8036.2(DIR) U8036.11(GND) U8036.12(GND) U8036.13(GND) U8036.14(B8) U8036.22(OEn) U8036.25(PP) U8037.2(DIR) U8037.11(GND) U8037.12(GND) U8037.13(GND) U8037.14(B8) U8037.22(OEn) U8037.25(PP) U8038.4(GND) U8039.4(GND) U8040.4(GND) ; also on sheet 4 5 6 7 8 9 10 11 12 13 14 15 16 23 25 26 27 28 29 30 31 32 34 35 36 37
VDD33_U3: C229.1 C231.1 L2.1 U3.22(VDD33)
VDD_FPDA: C3000.1 C3016.1 L3002.2 U3000.48(VDD33_A)
VDD_FPDB: C3009.1 C3021.1 L3003.2 U3000.29(VDD33_B)
VDDIO_FPD: C3007.1 C3008.1 C3018.1 C3019.1 C3020.1 C3022.1 L3000.2 L3001.2 U3000.13(VDDIO.3) U3000.24(VDDIO.2) U3000.38(VDDIO.1)
VDDIO_U3: C235.1 C236.1 L3.2 U3.30(VDDIO)
VIN_I2C_SCL: R1069.1 R9295.2 U8031.2(A0) ; also on sheet 7 31
VIN_I2C_SCL_3V3: R9301.2 U8038.2(A0) U8039.2(A0) U8040.2(A0) ; also on sheet 23 25 31
VIN_I2C_SDA: R1071.1 R9294.2 U8031.3(A1) ; also on sheet 7 31
VIN_I2C_SDA_3V3: R9300.2 U8038.3(A1) U8039.3(A1) U8040.3(A1) ; also on sheet 23 25 31
9122_AVCC: C6126.1 C6127.1 L3102.2(P2) U16.60(AVCC12.1) U16.66(AVCC12.2)
9122_CVCC: C3100.1 C3104.1 C3105.1 C3106.1 C6124.1 C6125.1 L3100.2(P2) U16.5(CVCC12.1) U16.12(CVCC12.3) U16.26(CVCC12.2) U16.42(CVCC12.4) U16.47(CVCC12.5) U16.53(CVCC12.6)
APT_CAM_BD0: U8034.3(A1) ; also on sheet 27
APT_CAM_BD1: U8034.4(A2) ; also on sheet 27
APT_CAM_BD2: U8037.6(A4) ; also on sheet 27
APT_CAM_BD3: U8037.5(A3) ; also on sheet 27
APT_CAM_BD4: U8034.6(A4) ; also on sheet 27
APT_CAM_BD5: U8034.5(A3) ; also on sheet 27
APT_CAM_BD6: U8034.8(A6) ; also on sheet 27
APT_CAM_BD7: U8034.7(A5) ; also on sheet 27
APT_CAM_BD8: U8034.10(A8) ; also on sheet 27
APT_CAM_BD9: U8034.9(A7) ; also on sheet 27
APT_CAM_BD10: U8037.4(A2) ; also on sheet 27
APT_CAM_BD11: U8037.3(A1) ; also on sheet 27
APT_CAM_BFRAME: U8037.8(A6) ; also on sheet 27
APT_CAM_BLINE: U8037.7(A5) ; also on sheet 27
APT_CAM_BPXCLK: R9390.1 ; also on sheet 27
APT_CAM_CLK: P4002.28 R4004.2
APT_CAM_RSTn_OD: P4002.18 R4020.1 R9400.1 TP8102.1(TP) ; also on sheet 27
APT_TRIGGER: R4027.1 R4028.2 U4003.3(A) ; also on sheet 8
BOARD_DET1: P4003.D30 R4056.2
C_APT_BD0: P4002.2 U8034.21(B1)
C_APT_BD1: P4002.1 U8034.20(B2)
C_APT_BD2: P4002.11 U8037.18(B4)
C_APT_BD3: P4002.12 U8037.19(B3)
C_APT_BD4: P4002.3 U8034.18(B4)
C_APT_BD5: P4002.4 U8034.19(B3)
C_APT_BD6: P4002.5 U8034.16(B6)
C_APT_BD7: P4002.6 U8034.17(B5)
C_APT_BD8: P4002.7 U8034.14(B8)
C_APT_BD9: P4002.8 U8034.15(B7)
C_APT_BD10: P4002.9 U8037.20(B2)
C_APT_BD11: P4002.10 U8037.21(B1)
C_APT_BFRAME: P4002.19 TP8100.1(TP) U8037.16(B6)
C_APT_BLINE: P4002.15 TP8101.1(TP) U8037.17(B5)
C_APT_BPXCLK: R4011.2 TP8099.1(TP) U8037.15(B7)
C_APT_I2C_SCL: P4002.21 R9397.2 U8040.7(B0)
C_APT_I2C_SDA: P4002.20 R9398.2 U8040.6(B1)
C_LI_D0: P4001.28 U101.7(B1)
C_LI_D1: P4001.27 U8032.14(B8)
C_LI_D2: P4001.24 U8032.15(B7)
C_LI_D3: P4001.23 U8032.16(B6)
C_LI_D4: P4001.22 U8032.17(B5)
C_LI_D5: P4001.21 U8032.18(B4)
C_LI_D6: P4001.20 U8032.19(B3)
C_LI_D7: P4001.19 U8032.20(B2)
C_LI_D8: P4001.18 U8032.21(B1)
C_LI_D9: P4001.17 U46.14(B8)
C_LI_D10: P4001.16 U46.15(B7)
C_LI_D11: P4001.15 U46.16(B6)
C_LI_D12: P4001.14 U46.17(B5)
C_LI_D13: P4001.13 U46.18(B4)
C_LI_DUAL_TRIGGER: P4001.35 R4065.1 U8033.19(B3)
C_LI_HSYNC: P4001.12 TP8094.1(TP) U46.19(B3)
C_LI_I2C_SCL: P4001.29 R9394.2 U8039.7(B0)
C_LI_I2C_SDA: P4001.30 R9395.2 U8039.6(B1)
C_LI_PCLK: R4010.2 TP8092.1(TP) U46.21(B1)
C_LI_SPI3_CS0: P4001.34 U8033.20(B2)
C_LI_SPI3_MISO: P4001.31 U101.6(B2)
C_LI_SPI3_MOSI: P4001.36 U8033.18(B4)
C_LI_SPI3_SCLK: P4001.32 U8033.21(B1)
C_LI_VSYNC: P4001.11 TP8093.1(TP) U46.20(B2)
C_OV_1HREF: P4000.13 TP8098.1(TP) U8036.21(B1)
C_OV_1PCLK: R4005.2 TP8096.1(TP) U8036.19(B3)
C_OV_1VSYNC: P4000.15 TP8097.1(TP) U8036.20(B2)
C_OV_1Y0: P4000.26 U8036.15(B7)
C_OV_1Y1: P4000.25 U8036.16(B6)
C_OV_1Y2: P4000.24 U8036.17(B5)
C_OV_1Y3: P4000.23 U8036.18(B4)
C_OV_1Y4: P4000.2 U8035.21(B1)
C_OV_1Y5: P4000.1 U8035.20(B2)
C_OV_1Y6: P4000.4 U8035.19(B3)
C_OV_1Y7: P4000.3 U8035.18(B4)
C_OV_1Y8: P4000.6 U8035.17(B5)
C_OV_1Y9: P4000.5 U8035.16(B6)
C_OV_1Y10: P4000.8 U8035.15(B7)
C_OV_1Y11: P4000.7 U8035.14(B8)
C_OV_I2C_SCL: P4000.14 R9391.2 U8038.7(B0)
C_OV_I2C_SDA: P4000.12 R9392.2 U8038.6(B1)
CAM1_D0: P4003.H13 ; also on sheet 27
CAM1_D1: P4003.G15 ; also on sheet 27
CAM1_D2: P4003.H11 ; also on sheet 27
CAM1_D3: P4003.H10 ; also on sheet 27
CAM1_D4: P4003.G10 ; also on sheet 27
CAM1_D5: P4003.G9 ; also on sheet 27
CAM1_D6: P4003.H20 ; also on sheet 27
CAM1_D7: P4003.H19 ; also on sheet 27
CAM1_D8: P4003.D18 ; also on sheet 27
CAM1_D9: P4003.D17 ; also on sheet 27
CAM1_D10: P4003.G3 ; also on sheet 27
CAM1_D11: P4003.G12 ; also on sheet 27
CAM1_D12: P4003.H28 ; also on sheet 27
CAM1_D13: P4003.H29 ; also on sheet 27
CAM1_D14: P4003.C22 ; also on sheet 27
CAM1_D15: P4003.C23 ; also on sheet 27
CAM1_D16: P4003.H16 ; also on sheet 27
CAM1_D17: P4003.C26 ; also on sheet 27
CAM1_D18: P4003.D4 ; also on sheet 27
CAM1_D19: P4003.D5 ; also on sheet 27
CAM1_D20: P4003.C2 ; also on sheet 27
CAM1_D21: P4003.C3 ; also on sheet 27
CAM1_D22: P4003.C6 ; also on sheet 27
CAM1_D23: P4003.C7 ; also on sheet 27
CAM1_DE: P4003.H25 TP8106.1(TP) ; also on sheet 27
CAM1_HS: P4003.G16 TP8105.1(TP) ; also on sheet 27
CAM1_PCLK: P4003.G7 TP8103.1(TP) ; also on sheet 27
CAM1_VS: P4003.G2 TP8104.1(TP) ; also on sheet 27
CAM2_D0: P4003.H14 ; also on sheet 27
CAM2_D1: P4003.D11 ; also on sheet 27
CAM2_D2: P4003.D9 ; also on sheet 27
CAM2_D3: P4003.D8 ; also on sheet 27
CAM2_D4: P4003.H5 ; also on sheet 27
CAM2_D5: P4003.H4 ; also on sheet 27
CAM2_D6: P4003.C15 ; also on sheet 27
CAM2_D7: P4003.C14 ; also on sheet 27
CAM2_D8: P4003.H8 ; also on sheet 27
CAM2_D9: P4003.H7 ; also on sheet 27
CAM2_D10: P4003.G18 ; also on sheet 27
CAM2_D11: P4003.G19 ; also on sheet 27
CAM2_HS: P4003.D12 TP8109.1(TP) ; also on sheet 27
CAM2_PCLK: P4003.G6 TP8107.1(TP) ; also on sheet 27
CAM2_VS: P4003.G13 TP8108.1(TP) ; also on sheet 27
CAM3_D0: P4003.H22 ; also on sheet 27
CAM3_D1: P4003.G30 ; also on sheet 27
CAM3_D2: P4003.C11 ; also on sheet 27
CAM3_D3: P4003.C10 ; also on sheet 27
CAM3_D4: P4003.G22 ; also on sheet 27
CAM3_D5: P4003.G21 ; also on sheet 27
CAM3_D6: P4003.G25 ; also on sheet 27
CAM3_D7: P4003.G24 ; also on sheet 27
CAM3_D8: P4003.D24 ; also on sheet 27
CAM3_D9: P4003.D23 ; also on sheet 27
CAM3_D10: P4003.D15 ; also on sheet 27
CAM3_D11: P4003.C18 ; also on sheet 27
CAM3_D12: P4003.G33 ; also on sheet 27
CAM3_D13: P4003.G34 ; also on sheet 27
CAM3_D14: P4003.G36 ; also on sheet 27
CAM3_D15: P4003.G37 ; also on sheet 27
CAM3_DE: P4003.H26 TP8113.1(TP) ; also on sheet 27
CAM3_HS: P4003.G31 TP8112.1(TP) ; also on sheet 27
CAM3_PCLK: P4003.D21 TP8110.1(TP) ; also on sheet 27
CAM3_VS: P4003.D14 TP8111.1(TP) ; also on sheet 27
CAM4_D0: P4003.H23 ; also on sheet 27
CAM4_D1: P4003.H37 ; also on sheet 27
CAM4_D2: P4003.H35 ; also on sheet 27
CAM4_D3: P4003.H34 ; also on sheet 27
CAM4_D4: P4003.G28 ; also on sheet 27
CAM4_D5: P4003.G27 ; also on sheet 27
CAM4_D6: P4003.H32 ; also on sheet 27
CAM4_D7: P4003.H31 ; also on sheet 27
CAM4_D8: P4003.D27 ; also on sheet 27
CAM4_D9: P4003.D26 ; also on sheet 27
CAM4_D10: P4003.C27 ; also on sheet 27
CAM4_D11: P4003.H17 ; also on sheet 27
CAM4_HS: P4003.H38 TP8116.1(TP) ; also on sheet 27
CAM4_PCLK: P4003.D20 TP8114.1(TP) ; also on sheet 27
CAM4_VS: P4003.C19 TP8115.1(TP) ; also on sheet 27
CI2CA: R3108.1(P1) R3114.2(P2) U16.72(CI2CA)
CSI2_I2C_SCL: J1002.25 R1058.2 R1068.1 U8031.7(B0)
CSI2_I2C_SDA: J1002.24 R1059.2 R1070.1 U8031.6(B1)
CSI2_REF_CLK: R1074.1 R1084.1 U1030.14(B8)
CSI2_RESETn: J1002.23 R1072.1 U1030.15(B7)
CSI2_SPI[1]_CS[0]n: J1002.32 R1062.1 U1030.21(B1)
CSI2_SPI[1]_MOSI: J1002.30 R1064.1 U1030.19(B3)
CSI2_SPI[1]_SCLK: J1002.31 R1066.1 U1030.20(B2)
FMC_GA0: P4003.C34 R4043.2 R4048.1
FMC_GA1: P4003.D35 R4042.2 R4044.1
FPD_B0: U3000.19(B0/O4) ; also on sheet 27
FPD_B1: U3000.18(B1/I2S_DB/O5) ; also on sheet 27
FPD_B2: U3000.17(B2) ; also on sheet 27
FPD_B3: U3000.14(B3) ; also on sheet 27
FPD_B4: U3000.12(B4) ; also on sheet 27
FPD_B5: U3000.11(B5) ; also on sheet 27
FPD_B6: U3000.10(B6) ; also on sheet 27
FPD_B7: U3000.9(B7) ; also on sheet 27
FPD_DE: TP8085.1(TP) U3000.6(DE) ; also on sheet 27
FPD_DOUT+: C5.2 P1.3
FPD_DOUT-: C6.2 P1.1
FPD_G0: U3000.28(G0/IO2) ; also on sheet 27
FPD_G1: U3000.27(G1/IO3) ; also on sheet 27
FPD_G2: U3000.26(G2) ; also on sheet 27
FPD_G3: U3000.25(G3) ; also on sheet 27
FPD_G4: U3000.23(G4) ; also on sheet 27
FPD_G5: U3000.22(G5) ; also on sheet 27
FPD_G6: U3000.21(G6) ; also on sheet 27
FPD_G7: U3000.20(G7) ; also on sheet 27
FPD_HS: TP8083.1(TP) U3000.8(HS) ; also on sheet 27
FPD_LINK_DB_DET: P4003.D31 ; also on sheet 8
FPD_PCLK: TP8086.1(TP) U3000.5(PCLK) ; also on sheet 27
FPD_R0: U3000.41(R0/IO0) ; also on sheet 27
FPD_R1: U3000.40(R1/IO1) ; also on sheet 27
FPD_R2: U3000.39(R2) ; also on sheet 27
FPD_R3: U3000.37(R3) ; also on sheet 27
FPD_R4: U3000.36(R4) ; also on sheet 27
FPD_R5: U3000.35(R5) ; also on sheet 27
FPD_R6: U3000.34(R6) ; also on sheet 27
FPD_R7: U3000.33(R7) ; also on sheet 27
FPD_VS: TP8084.1(TP) U3000.7(VS) ; also on sheet 27
H_CSI2_0_DX0: J1002.8 P15.5 ; also on sheet 4
H_CSI2_0_DX1: J1002.11 P15.9 ; also on sheet 4
H_CSI2_0_DX2: J1002.14 P15.13 ; also on sheet 4
H_CSI2_0_DX3: J1002.17 P15.17 ; also on sheet 4
H_CSI2_0_DX4: J1002.20 P15.21 ; also on sheet 4
H_CSI2_0_DY0: J1002.9 P15.7 ; also on sheet 4
H_CSI2_0_DY1: J1002.12 P15.11 ; also on sheet 4
H_CSI2_0_DY2: J1002.15 P15.15 ; also on sheet 4
H_CSI2_0_DY3: J1002.18 P15.19 ; also on sheet 4
H_CSI2_0_DY4: J1002.21 P15.23 ; also on sheet 4
HDMI_CEC_D: R3109.1(P1) U16.50(CEC_D) ; also on sheet 8
HDMI_CT_HPD: R9302.2 ; also on sheet 8
HDMI_D0: U16.32(D0) ; also on sheet 26
HDMI_D1: U16.31(D1) ; also on sheet 26
HDMI_D2: U16.30(D2) ; also on sheet 26
HDMI_D3: U16.29(D3) ; also on sheet 26
HDMI_D4: U16.28(D4) ; also on sheet 26
HDMI_D5: U16.27(D5) ; also on sheet 26
HDMI_D6: U16.25(D6) ; also on sheet 26
HDMI_D7: U16.24(D7) ; also on sheet 26
HDMI_D8: U16.23(D8) ; also on sheet 26
HDMI_D9: U16.20(D9) ; also on sheet 26
HDMI_D10: U16.19(D10) ; also on sheet 26
HDMI_D11: U16.18(D11) ; also on sheet 26
HDMI_D12: U16.17(D12) ; also on sheet 26
HDMI_D13: U16.16(D13) ; also on sheet 26
HDMI_D14: U16.15(D14) ; also on sheet 26
HDMI_D15: U16.14(D15) ; also on sheet 26
HDMI_D16: U16.13(D16) ; also on sheet 26
HDMI_D17: U16.11(D17) ; also on sheet 26
HDMI_D18: U16.10(D18) ; also on sheet 26
HDMI_D19: U16.9(D19) ; also on sheet 26
HDMI_D20: U16.8(D20) ; also on sheet 26
HDMI_D21: U16.7(D21) ; also on sheet 26
HDMI_D22: U16.6(D22) ; also on sheet 26
HDMI_D23: U16.4(D23) ; also on sheet 26
HDMI_DEN: TP8074.1(TP) U16.33(DE) ; also on sheet 26
HDMI_HSYNC: TP8072.1(TP) U16.34(HSYNC) ; also on sheet 26
HDMI_INTn: R3111.2(P2) U16.52(INT) ; also on sheet 26
HDMI_LS_OE: R9303.2 ; also on sheet 8
HDMI_PCLK: TP8071.1(TP) U16.22(IDCK) ; also on sheet 26
HDMI_RSTn: TP8070.1(TP) U16.51(RESETn) ; also on sheet 26
HDMI_VSYNC: TP8073.1(TP) U16.35(VSYNC) ; also on sheet 26
HPD: R3103.2(P2) U16.54(HPD) U3101.3(HPD_A)
LI_CAM_D0: U101.2(A1) ; also on sheet 27
LI_CAM_D1: U8032.10(A8) ; also on sheet 27
LI_CAM_D2: U8032.9(A7) ; also on sheet 27
LI_CAM_D3: U8032.8(A6) ; also on sheet 27
LI_CAM_D4: U8032.7(A5) ; also on sheet 27
LI_CAM_D5: U8032.6(A4) ; also on sheet 27
LI_CAM_D6: U8032.5(A3) ; also on sheet 27
LI_CAM_D7: U8032.4(A2) ; also on sheet 27
LI_CAM_D8: U8032.3(A1) ; also on sheet 27
LI_CAM_D9: U46.10(A8) ; also on sheet 27
LI_CAM_D10: U46.9(A7) ; also on sheet 27
LI_CAM_D11: U46.8(A6) ; also on sheet 27
LI_CAM_D12: U46.7(A5) ; also on sheet 27
LI_CAM_D13: U46.6(A4) ; also on sheet 27
LI_CAM_RESETn_OD: P4001.33 R4009.2 TP8095.1(TP) ; also on sheet 27
LI_DUAL_Trigger: U8033.5(A3) ; also on sheet 8
LI_EXT_CLK: P4001.7 R4003.1
LI_HSYNC: U46.5(A3) ; also on sheet 27
LI_PCLK: R9388.1 ; also on sheet 27
LI_VSYNC: U46.4(A2) ; also on sheet 27
MJB1_TIMER1: P4003.D33 ; also on sheet 32
MJB1_TIMER2: P4003.D34 ; also on sheet 32
MJB1_TIMER3: P4003.D29 ; also on sheet 32
OV_1CCLK: P4000.20 R4000.2
OV_1HREF: U8036.3(A1) ; also on sheet 27
OV_1PCLK: R9389.1 ; also on sheet 27
OV_1VSYNC: U8036.4(A2) ; also on sheet 27
OV_1Y0: U8036.9(A7) ; also on sheet 27
OV_1Y1: U8036.8(A6) ; also on sheet 27
OV_1Y2: U8036.7(A5) ; also on sheet 27
OV_1Y3: U8036.6(A4) ; also on sheet 27
OV_1Y4: U8035.3(A1) ; also on sheet 27
OV_1Y5: U8035.4(A2) ; also on sheet 27
OV_1Y6: U8035.5(A3) ; also on sheet 27
OV_1Y7: U8035.6(A4) ; also on sheet 27
OV_1Y8: U8035.7(A5) ; also on sheet 27
OV_1Y9: U8035.8(A6) ; also on sheet 27
OV_1Y10: U8035.9(A7) ; also on sheet 27
OV_1Y11: U8035.10(A8) ; also on sheet 27
OV_PWDN: R4006.2 ; also on sheet 27
QSH_REF_CLK: P15.10 R1074.2 R1075.2
QSH_RESETn: P15.14 R1072.2 R1073.2
QSH_SCL: P15.2 R1068.2 R1069.2
QSH_SDA: P15.4 R1070.2 R1071.2
QSH_SPI[1]_CS[0]n: P15.22 R1062.2 R1063.2
QSH_SPI[1]_MOSI: P15.18 R1064.2 R1065.2
QSH_SPI[1]_SCLK: P15.20 R1066.2 R1067.2
RIN+: C3014.1 U3000.49(RIN+)
RIN-: C3015.1 U3000.50(RIN-)
RIN_AC+: C3014.2 FL3000.1
RIN_AC-: C3015.2 FL3000.4
RIN_C+: FL3000.2 P3000.2
RIN_C-: FL3000.3 P3000.4
RMB1_SPI3_CS0: U8033.4(A2) ; also on sheet 32
RMB1_SPI3_CS1: R1063.1 U1030.3(A1) ; also on sheet 32
RMB1_SPI3_MISO: U101.3(A2) ; also on sheet 32
RMB1_SPI3_MOSI: R1065.1 U1030.5(A3) U8033.6(A4) ; also on sheet 32
RMB1_SPI3_SCLK: R1067.1 U1030.4(A2) U8033.3(A1) ; also on sheet 32
RMB3_TIMER7: P4003.D1 ; also on sheet 32
RSTOUTn: R1073.1 U1030.9(A7) ; also on sheet 4 8 9 26
SI_CEC_A: R3104.1 U16.71(CEC_A) U3101.24(CEC_A)
SWG: R3100.2 U16.56(EXT_SWING)
TX0+: P3100.7(D0+) U16.62(TX0+) U3101.17(D0+)
TX0-: P3100.9(D0-) U16.61(TX0-) U3101.16(D0-)
TX1+: P3100.4(D1+) U16.65(TX1+) U3101.20(D1+)
TX1-: P3100.6(D1-) U16.64(TX1-) U3101.19(D1-)
TX2+: P3100.1(D2+) U16.68(TX2+) U3101.22(D2+)
TX2-: P3100.3(D2-) U16.67(TX2-) U3101.21(D2-)
TX_DSCL: R3101.1 U16.49(DSCL) U3101.1(SCL_A)
TX_DSDA: R3102.2(P2) U16.48(DSDA) U3101.2(SDA_A)
TXC+: P3100.10(CK+) U16.59(TXC+) U3101.15(CLK+)
TXC-: P3100.12(CK-) U16.58(TXC-) U3101.14(CLK-)
V_1p2: C8081.1 C8082.1 L3100.1(P1) L3102.1(P1) R9191.1 U8015.9(VOUT1) U8015.10(VOUT2)
V_DC_FPDLINK_12V: L4005.2 L4006.2 P4003.C35 P4003.C37
V_U4: C1062.1 L1006.1 U4.4(VCC)
V_U4000: C4018.1 L4000.1 U4000.4(VCC)
V_U4002: C4019.1 L4002.1 U4002.4(VCC)
V_U4004: C4034.1 L4004.1 U4004.4(VCC)
VCAPHS_U3: C7.1 U3.17(CAPHS12)
VCAPIS12_U3000: C3002.1 U3000.58(CAPIS12)
VCAPL12_U3: C13.1 C234.1 U3.7(CAPL12)
VCAPL12_U3000: C3006.1 C3017.1 U3000.4(CAPL12)
VCAPP12_U3: C8.1 U3.14(CAPP12)
VCAPP12_U3000: C3003.1 U3000.57(CAPP12)
VCAPR12_U3000: C3004.1 U3000.55(CAPR12)
VIO_9122: C3101.1 C3102.1 C3103.1 L3101.2(P2) U16.3(IOVCC.1) U16.21(IOVCC.2) U16.46(IOVCC.3)
VIO_APT: C8166.1 C8167.1 C8183.2 JP6.2 L4004.2 R4020.2 R9397.1 R9398.1 R9400.2 RJ28.2 U4004.1(EN) U8034.23(VCCB) U8034.24(VCCB) U8037.23(VCCB) U8037.24(VCCB) U8040.8(VCCB)
VIO_LI: C8175.1 C8176.1 C8177.1 C8181.2 JP5.2 L4002.2 R4009.1 R9394.1 R9395.1 RJ26.2 U46.23(VCCB) U46.24(VCCB) U101.8(VCCB) U4002.1(EN) U8032.23(VCCB) U8032.24(VCCB) U8033.23(VCCB) U8033.24(VCCB) U8039.8(VCCB)
VIO_OV: C8168.1 C8169.1 C8179.2 JP4.2 L4000.2 R4007.1 R9391.1 R9392.1 RJ27.2 U4000.1(EN) U8035.23(VCCB) U8035.24(VCCB) U8036.23(VCCB) U8036.24(VCCB) U8038.8(VCCB)
VOFPD_CLK: TP8082.1(TP) U3.10(PCLK) ; also on sheet 26
VOFPD_D0: U3.43(B0/O4) ; also on sheet 26
VOFPD_D1: U3.44(B1/I2S_DB/O5) ; also on sheet 26
VOFPD_D2: U3.45(B2) ; also on sheet 26
VOFPD_D3: U3.46(B3) ; also on sheet 26
VOFPD_D4: U3.47(B4) ; also on sheet 26
VOFPD_D5: U3.48(B5) ; also on sheet 26
VOFPD_D6: U3.1(B6) ; also on sheet 26
VOFPD_D7: U3.2(B7) ; also on sheet 26
VOFPD_D8: U3.35(G0/IO2) ; also on sheet 26
VOFPD_D9: U3.36(G1/IO3) ; also on sheet 26
VOFPD_D10: U3.37(G2) ; also on sheet 26
VOFPD_D11: U3.38(G3) ; also on sheet 26
VOFPD_D12: U3.39(G4) ; also on sheet 26
VOFPD_D13: U3.40(G5) ; also on sheet 26
VOFPD_D14: U3.41(G6) ; also on sheet 26
VOFPD_D15: U3.42(G7) ; also on sheet 26
VOFPD_D16: U3.25(R0/IO0) ; also on sheet 26
VOFPD_D17: U3.26(R1/IO1) ; also on sheet 26
VOFPD_D18: U3.27(R2) ; also on sheet 26
VOFPD_D19: U3.28(R3) ; also on sheet 26
VOFPD_D20: U3.29(R4) ; also on sheet 26
VOFPD_D21: U3.32(R5) ; also on sheet 26
VOFPD_D22: U3.33(R6) ; also on sheet 26
VOFPD_D23: U3.34(R7) ; also on sheet 26
VOFPD_DE: TP8081.1(TP) U3.5(DE) ; also on sheet 26
VOFPD_HSYNC: TP8079.1(TP) U3.3(HS) ; also on sheet 26
VOFPD_INTB: R22.2 U3.31(INTB) ; also on sheet 26
VOFPD_VSYNC: TP8080.1(TP) U3.4(VS) ; also on sheet 26
VOUT_I2C_SCL: R9286.2 ; also on sheet 7 16 31
VOUT_I2C_SCL_3V3: R9289.2 ; also on sheet 31
VOUT_I2C_SDA: R9287.2 ; also on sheet 7 16 31
VOUT_I2C_SDA_3V3: R9288.2 ; also on sheet 31
VPRH_1V8: C1064.1 C4033.1 C8159.2 J1002.4 J1002.5 JP4.3 JP5.3 JP6.3 P15.38 P15.40 R1058.1 R1059.1 RJ26.3 RJ27.3 RJ28.3 U1030.23(VCCB) U1030.24(VCCB) U4003.6(VCCB) U8031.8(VCCB) ; also on sheet 6 14 15 16
VPRH_3V3: C3108.1 C8084.1 J1002.1 J1002.2 J1002.3 L2.2 L3002.1 L3003.1 P15.30 P15.32 P15.34 P15.36 P4001.1 P4001.2 P4001.3 P4003.D32 P4003.D36 P4003.D38 P4003.D40 R20.1 R332.1 R3010.1 R3016.1 R3101.2 R3102.1(P1) R3103.1(P1) R3104.2 R3105.2 R3115.1 R3116.1 R4042.1 R4043.1 R4056.1 U3101.23(VCCA) U8015.1(IN1) U8015.2(IN2) U8015.4(BIAS) U8015.5(EN) ; also on sheet 8 9 11 15 16 23 25 30 31 32 34 35
VPRH_5V0: C3107.1 C4000.1 C4009.1 P4000.19 P4000.21 P4001.4 P4001.5 P4002.23 P4002.24 R3107.2 R3110.2 R3112.2 U3101.10(VCC5V) ; also on sheet 14 16 23 25 26 35
VPRH_12V0: L4005.1 L4006.1 ; also on sheet 7 37
VPRH_DV: C1063.2 C4032.1 C8160.1 C8164.1 C8165.1 C8170.1 C8171.1 C8172.1 C8173.1 C8174.1 C8178.1 C8180.1 C8182.1 JP4.1 JP5.1 JP6.1 L3.1 L1006.2 L3000.1 L3001.1 L3101.1(P1) R8.1 R22.1 R1083.2 R3001.1 R3004.1 R3007.1 R3013.1 R3015.1 R3108.2(P2) R3109.2(P2) R3111.1(P1) R4028.1 R9229.2(P2) R9377.1 R9393.1 R9396.1 R9399.1 RJ26.1 RJ27.1 RJ28.1 U4.1(EN) U46.1(VCCA) U101.1(VCCA) U1030.1(VCCA) U1030.2(DIR) U4003.1(VCCA) U4003.5(DIR) U8031.1(VCCA) U8032.1(VCCA) U8033.1(VCCA) U8033.2(DIR) U8034.1(VCCA) U8035.1(VCCA) U8036.1(VCCA) U8037.1(VCCA) U8038.1(VCCA) U8039.1(VCCA) U8040.1(VCCA) ; also on sheet 4 7 8 9 10 11 13 15 16 23 26 27 28 31 35 36
N17473174: C215.2 P1.2
N17473178: C216.1 P1.4
N24431145: J1002.26 R1084.2
N24578842: R3005.1 R3015.2 U3000.31(OEN)
N24578844: R3001.2 R3011.1 U3000.46(OSS_SEL)
N24578846: R3004.2 R3014.1 U3000.44(BISTEN)
N24578850: R3006.1 R3016.2 U3000.15(MODE_SEL)
N24578900: R3000.1 R3010.2 U3000.56(IDX)
N24578927: R3007.2 TP8087.1(TP) U3000.16(BISTC/INTB_IN)
N24579024: TP8088.1(TP) U3000.32(LOCK)
N24579038: TP8089.1(TP) U3000.42(PAS)
N24579079: C3012.2 R3009.1 TP8091.1(TP)
N24579081: C3013.2 R3009.2 TP8090.1(TP)
N24579087: C3012.1 U3000.52(CMLOUTP)
N24579093: C3013.1 U3000.53(CMLOUTN)
N24579114: C3001.1 R3013.2 U3000.59(PDB)
N24579969: C3010.2 P3000.3
N24579973: C3011.1 P3000.1
N24579997: C3005.1 U3000.51(CMF)
N24600228: P3100.13(CE_REMOTE) R3105.1 U3101.6(CEC_B)
N24600234: P3100.15(DDC_CLK) R3107.1 U3101.7(SCL_B)
N24600238: P3100.16(DDC_DATA) R3110.1 U3101.8(SDA_B)
N24600242: P3100.19(HP_DET) R3112.1 R3113.1 U3101.9(HPD_B)
N24600346: R3116.2 R9303.1 U3101.4(LS_OE)
N24600356: R3115.2 R9302.1 U3101.11(CT_HPD)
N24601326: C3109.1 P3100.18(+5V) U3101.12(5V_OUT)
N24975205: R4003.2 U4002.3(OUT)
N24975593: P4001.9 R4010.1
N24976092: R4000.1 U4000.3(OUT)
N24976112: P4000.10 R4006.1 R4007.2 R4008.1
N24976132: P4000.17 R4005.1
N24980153: P4003.C30 R9295.1
N24980156: P4003.C31 R9294.1
N25117996: R3106.1 U16.55(RSVDL)
N25118001: R3117.1 U16.70(VDDQ)
N25118379: R3125.1 R9229.1(P1) U16.69(IO_SEL)
N25578138: C8083.1 U8015.7(SS)
N25578142: C8082.2 R9191.2 R9193.1 U8015.8(FB)
N26381824: R9286.1 U16.1(CSCL)
N26381827: R9287.1 U16.2(CSDA)
N26381890: R9300.1 U3000.2(SDA)
N26381893: R9301.1 U3000.3(SCL)
N27060036: R9377.2 U8031.5(OE)
N27300821: R9388.2 U46.3(A1)
N27303907: P4002.31 U4003.4(B)
N27304307: R4004.1 U4004.3(OUT)
N27304311: P4002.25 R4011.1
N27306120: R9389.2 U8036.5(A3)
N27308272: R9390.2 U8037.9(A7)
N27325143: R9393.2 U8038.5(OE)
N27326507: R9396.2 U8039.5(OE)
N27333386: R9399.2 U8040.5(OE)
N32733566: R332.2 R333.1 U3.24(MODE_SEL)
N32835273: C232.1 U3.23(CMF)
N32856854: C5.1 U3.20(DOUT+)
N32861613: C6.1 U3.19(DOUT-)
N32916975: R20.2 R338.1 U3.6(IDX)
N32962376: R9289.1 U3.8(SCL)
N32969558: R9288.1 U3.9(SDA)
N33151523: R10.1 U3.11(I2S_DA/O6)
N33156530: R9.1 U3.12(I2S_WC/O7)
N33159038: R11.1 U3.13(I2S_CLK/O8)
N33161549: C228.1 R8.2 U3.21(PDB)

Not connected (* = marked no-connect by the designer): J1002 27* 28* 35* 36*; MHC1 1(TP); MHC2 1(TP); MHC3 1(TP); MHC4 1(TP); MHC4000 1(TP); MHC4001 1(TP); P15 1 3 6 8 25 26 27 28 29 31 33 35 37 39; P3100 14(NC.14)*; P4000 9* 11* 27* 28* 29* 30*; P4002 16 17* 22*; P4003 C39* G39* H1* H40*; U3 16(NC.16); U16 36(SPDIF)* 37(SD3)* 38(MCLK)* 39(SD2)* 40(SD1)* 41(SD0)* 44(WS)* 45(SCK)*; U1030 16(B6)* 17(B5)* 18(B4)*; U3000 1(I2S_CLK/O8) 30(I2S_WC/O7) 45(I2S_DA/O6) 54(NC.54) 60(MCLK); U8015 3(PG); U8033 7(A5) 8(A6) 9(A7) 10(A8); U8036 10(A8); U8037 10(A8)

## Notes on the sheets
sheet 17
- VOUT = 0.8 * ( 1+Rtop/Rbottom )
- 100 OHM DIFF 4 PLACES
- THE HDMI I/O VOLTAGE LEVELS
  NEED TO BE RESOLVED.  NOT
  100% CLEAR 9022A
  DSCL/DSDA/CEC_A/HPD SUPPORT
  1.8V. THE EXAMPLES AND I/O
  VTH+/- INDICATE THEY DO NOT.
  THE TPD12S016 WILL SUPPORT
  1.8V I/O.
- CI2CA sets I2C Address:
- HIGH: 0x76  (SELECTED)
- LOW: 0x72
sheet 18
- TRANSMIT USES 1 DATA - 3 DATA +
- 100 OHM
- 100 OHM
- XMIT - PINS 1-3
  RECV - PINS 2-4
- I2C IS REFERENCED TO VDD33, NOT VDDIO
sheet 19
- 100 OHM
- 100 OHM
- XMIT - PINS 1-3
  RECV - PINS 2-4
- CHECK STRAPS
- I2C IS REFERENCED TO VDD33, NOT VDDIO
- STATUS LOCK AND ERROR FREE
sheet 20
- OPTIONAL
- SPI_SDO
- SPI_SDI
sheet 21
- THE SAMTEC CONNECTOR PINNING IS H-G-D-C BOTTOM VIEW.  THE FOLLOWING ARRANGEMENT IS PER THE TI SPECIFICATION.  THE PINNING DOES MATCH THE FMC TABLE 2.2 AND 2.3.
sheet 22
- CLOCK LANE
- OPTIONAL
